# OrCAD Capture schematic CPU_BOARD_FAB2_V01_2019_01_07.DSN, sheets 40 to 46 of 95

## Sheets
40 012 RESET BLOCK DIAGRAM
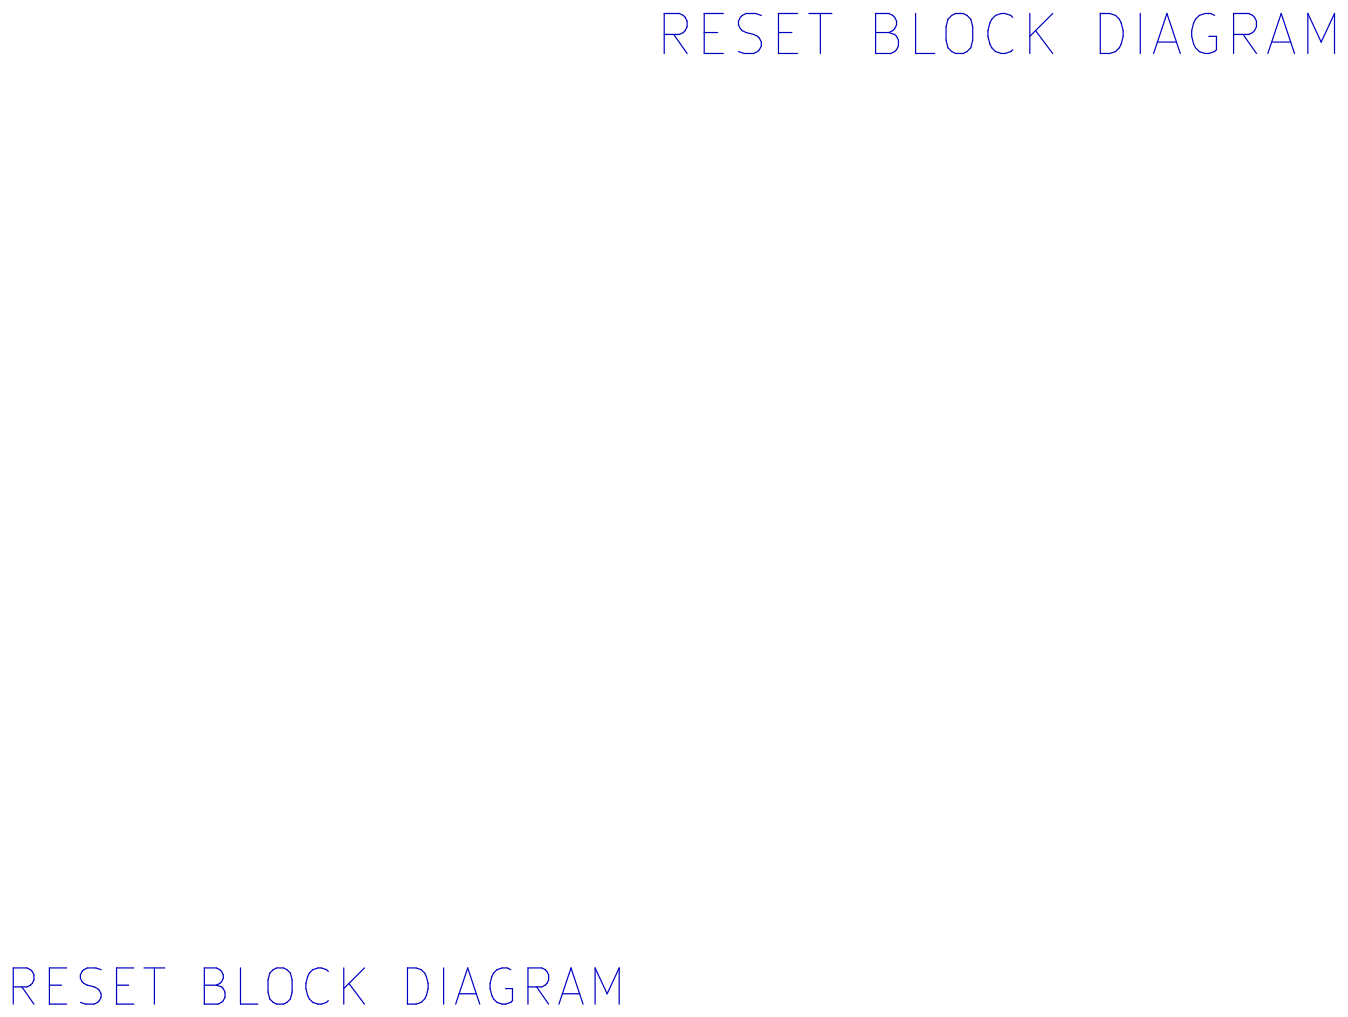
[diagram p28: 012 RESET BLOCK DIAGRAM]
41 016 BDE STRAPPING_1: size B
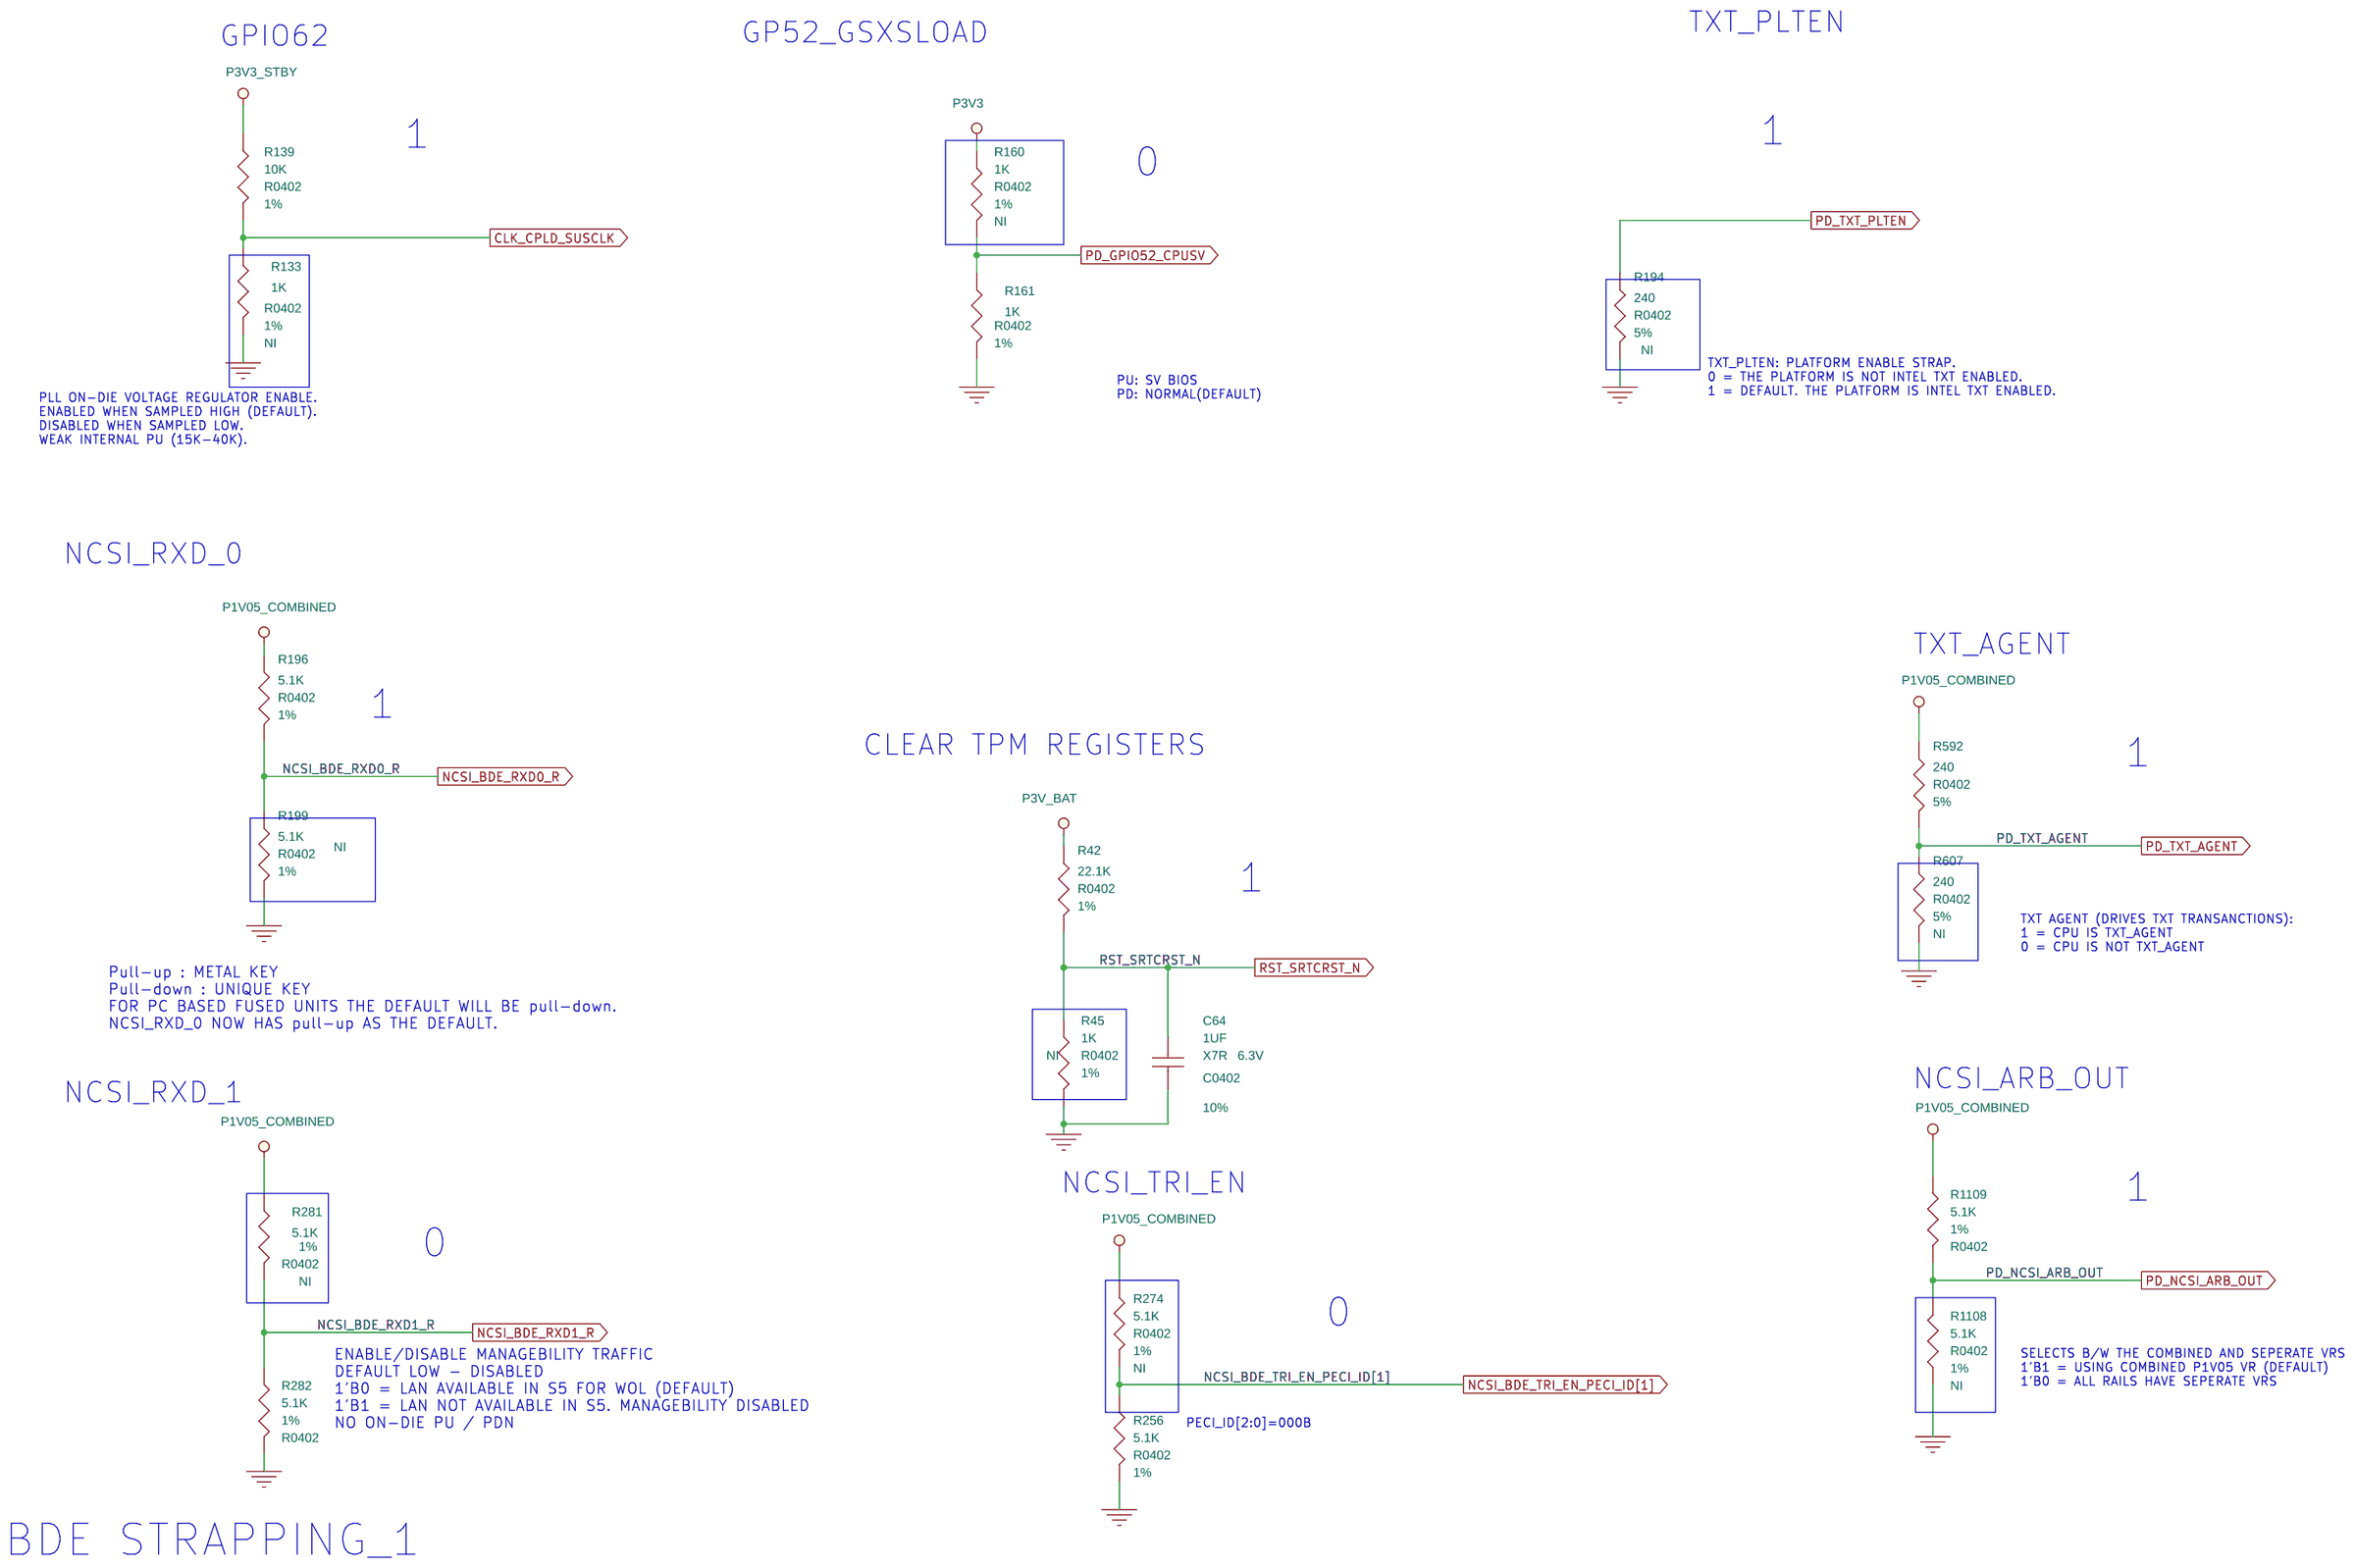
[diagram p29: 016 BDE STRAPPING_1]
42 017 BDE STRAPPING_2: size B
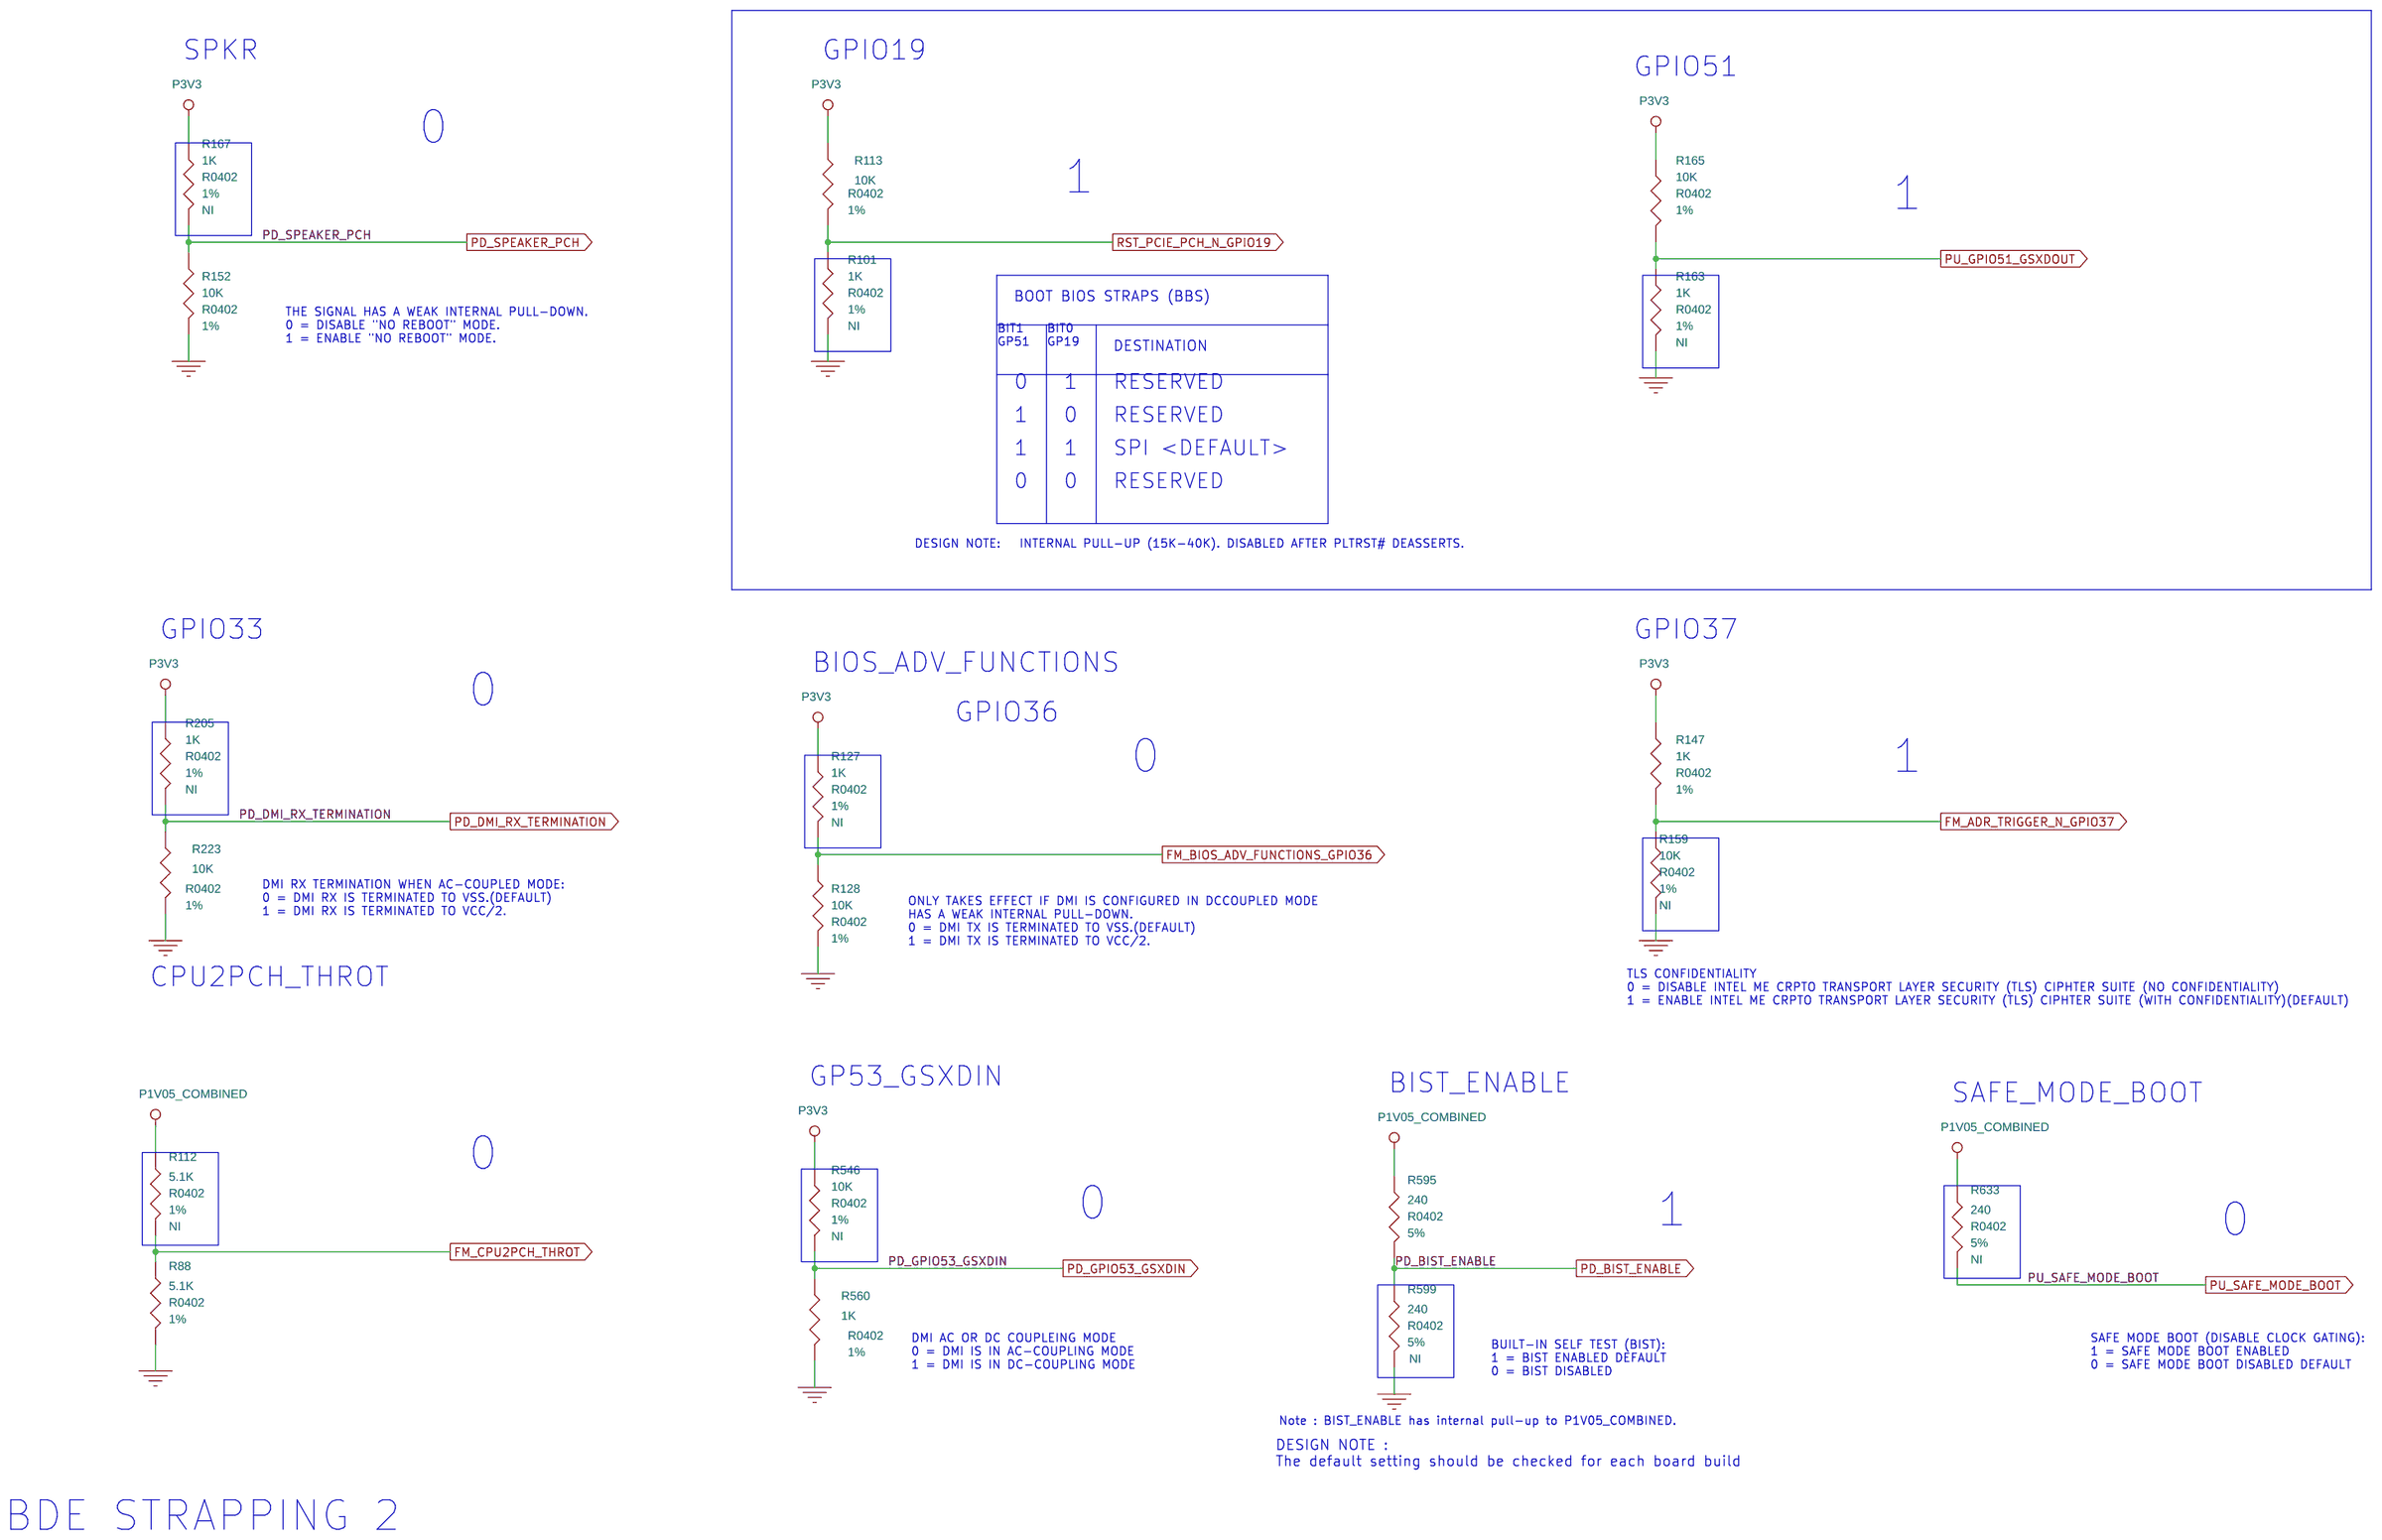
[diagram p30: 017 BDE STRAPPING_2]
43 018 BDX-DE DDR4 CHANNEL A: size B
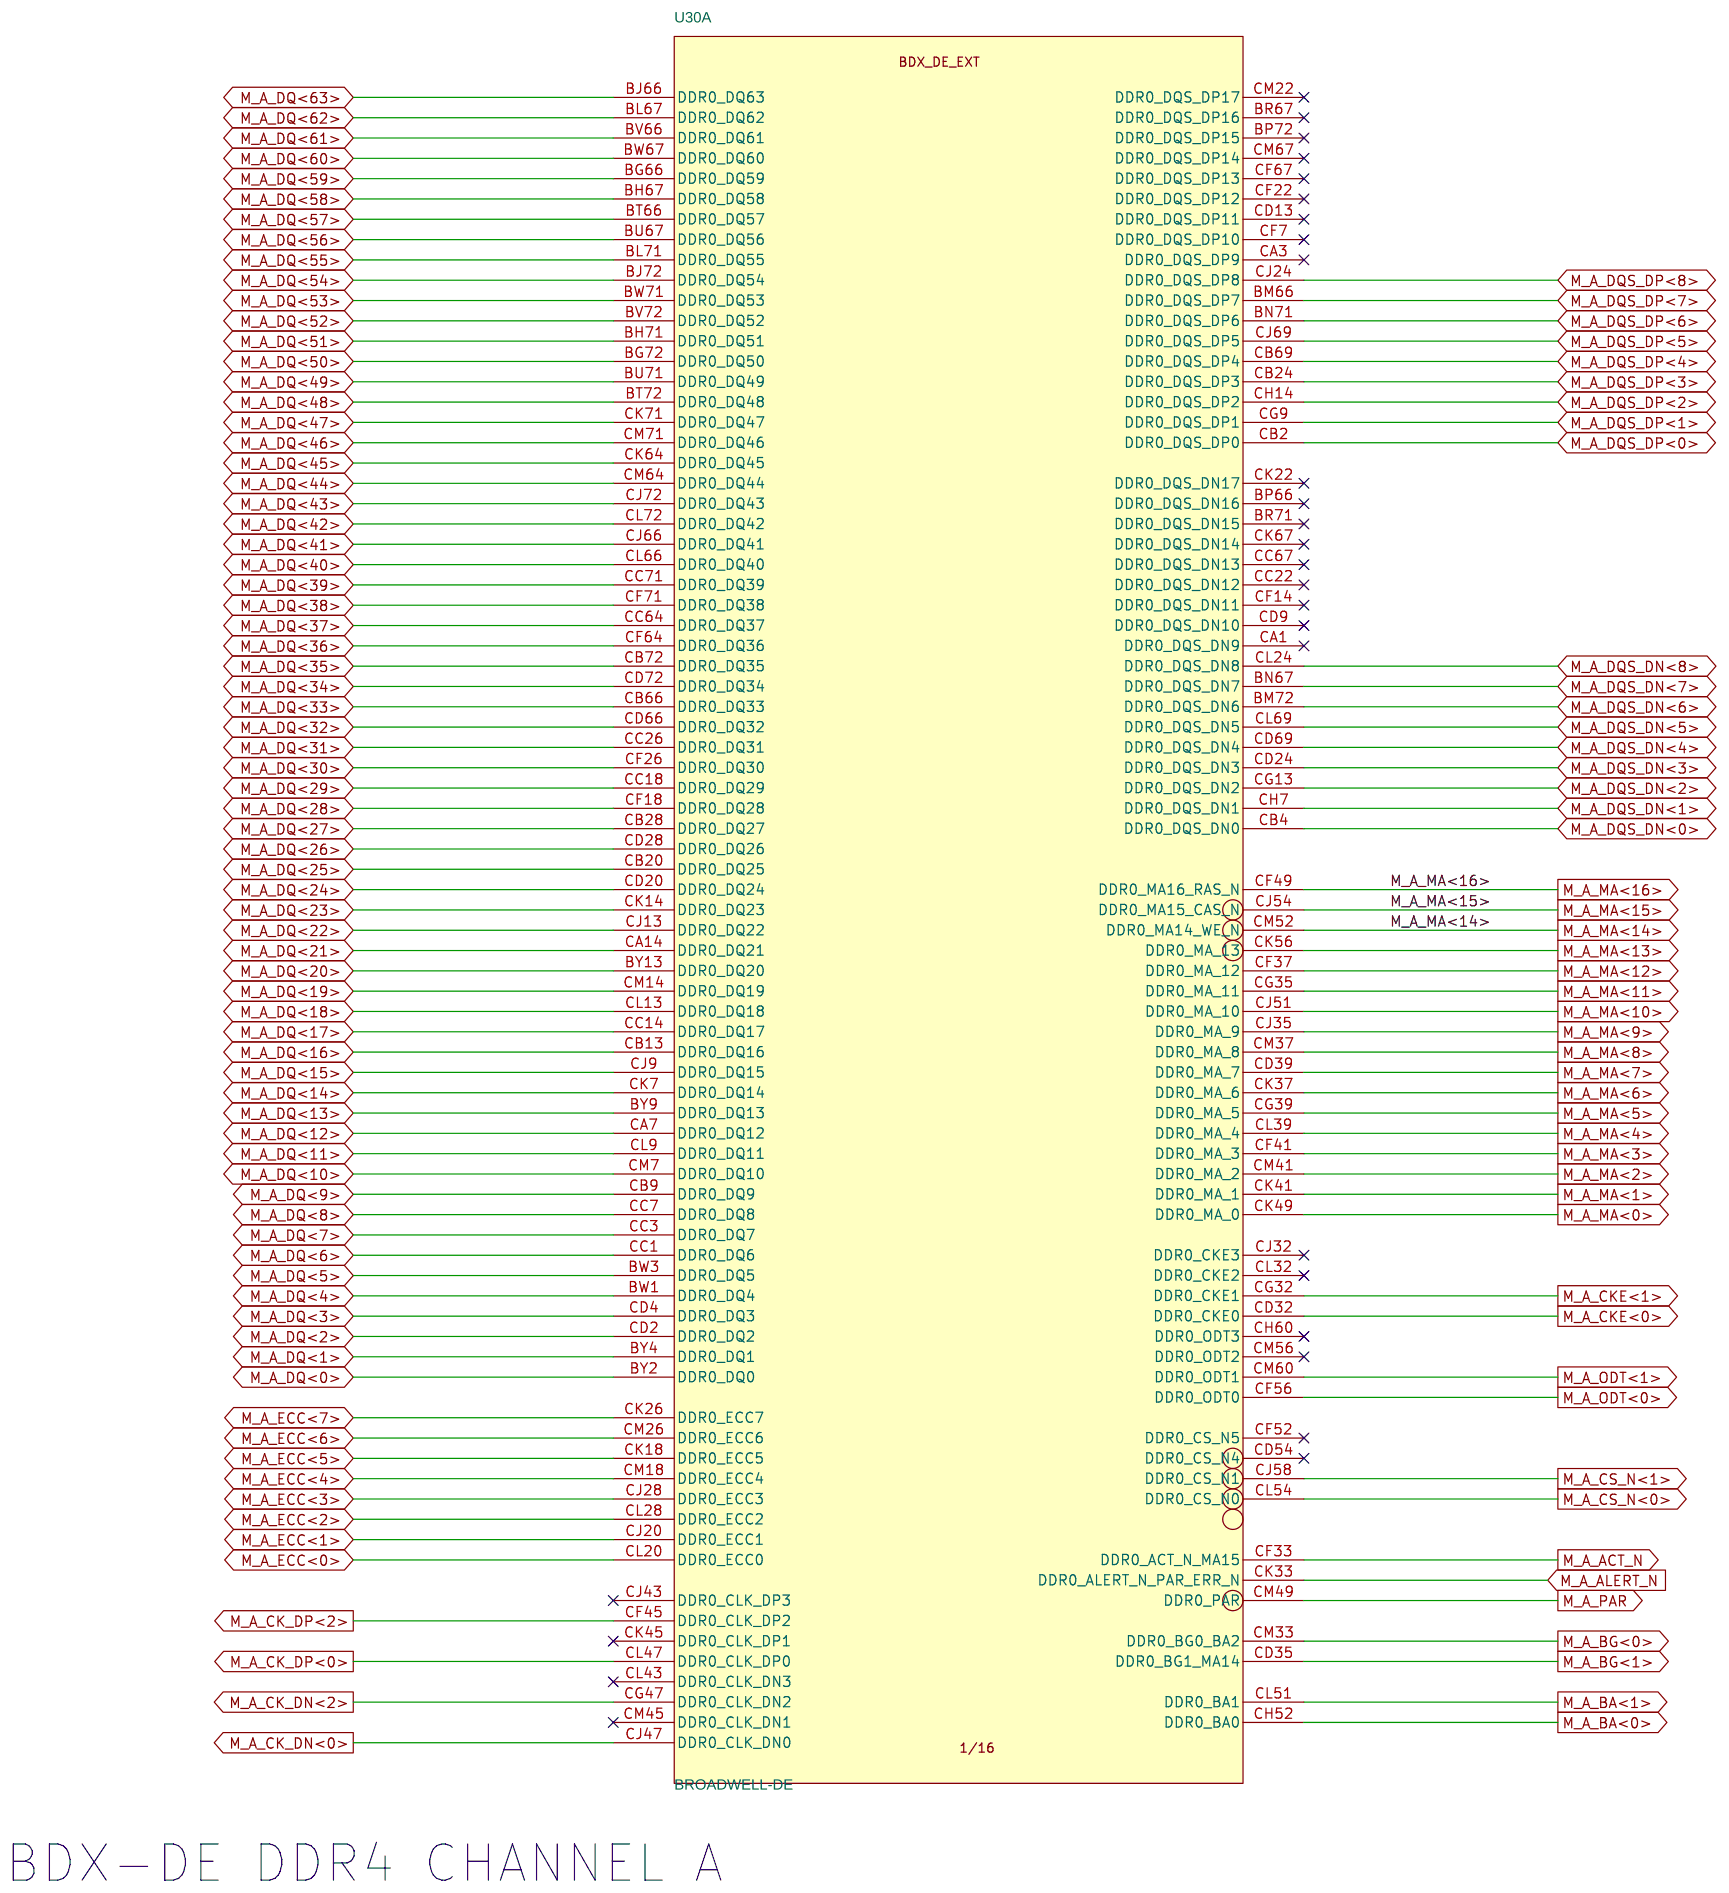
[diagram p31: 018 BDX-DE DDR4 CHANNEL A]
44 019 BDX-DE DDR4 CHANNEL B: size B
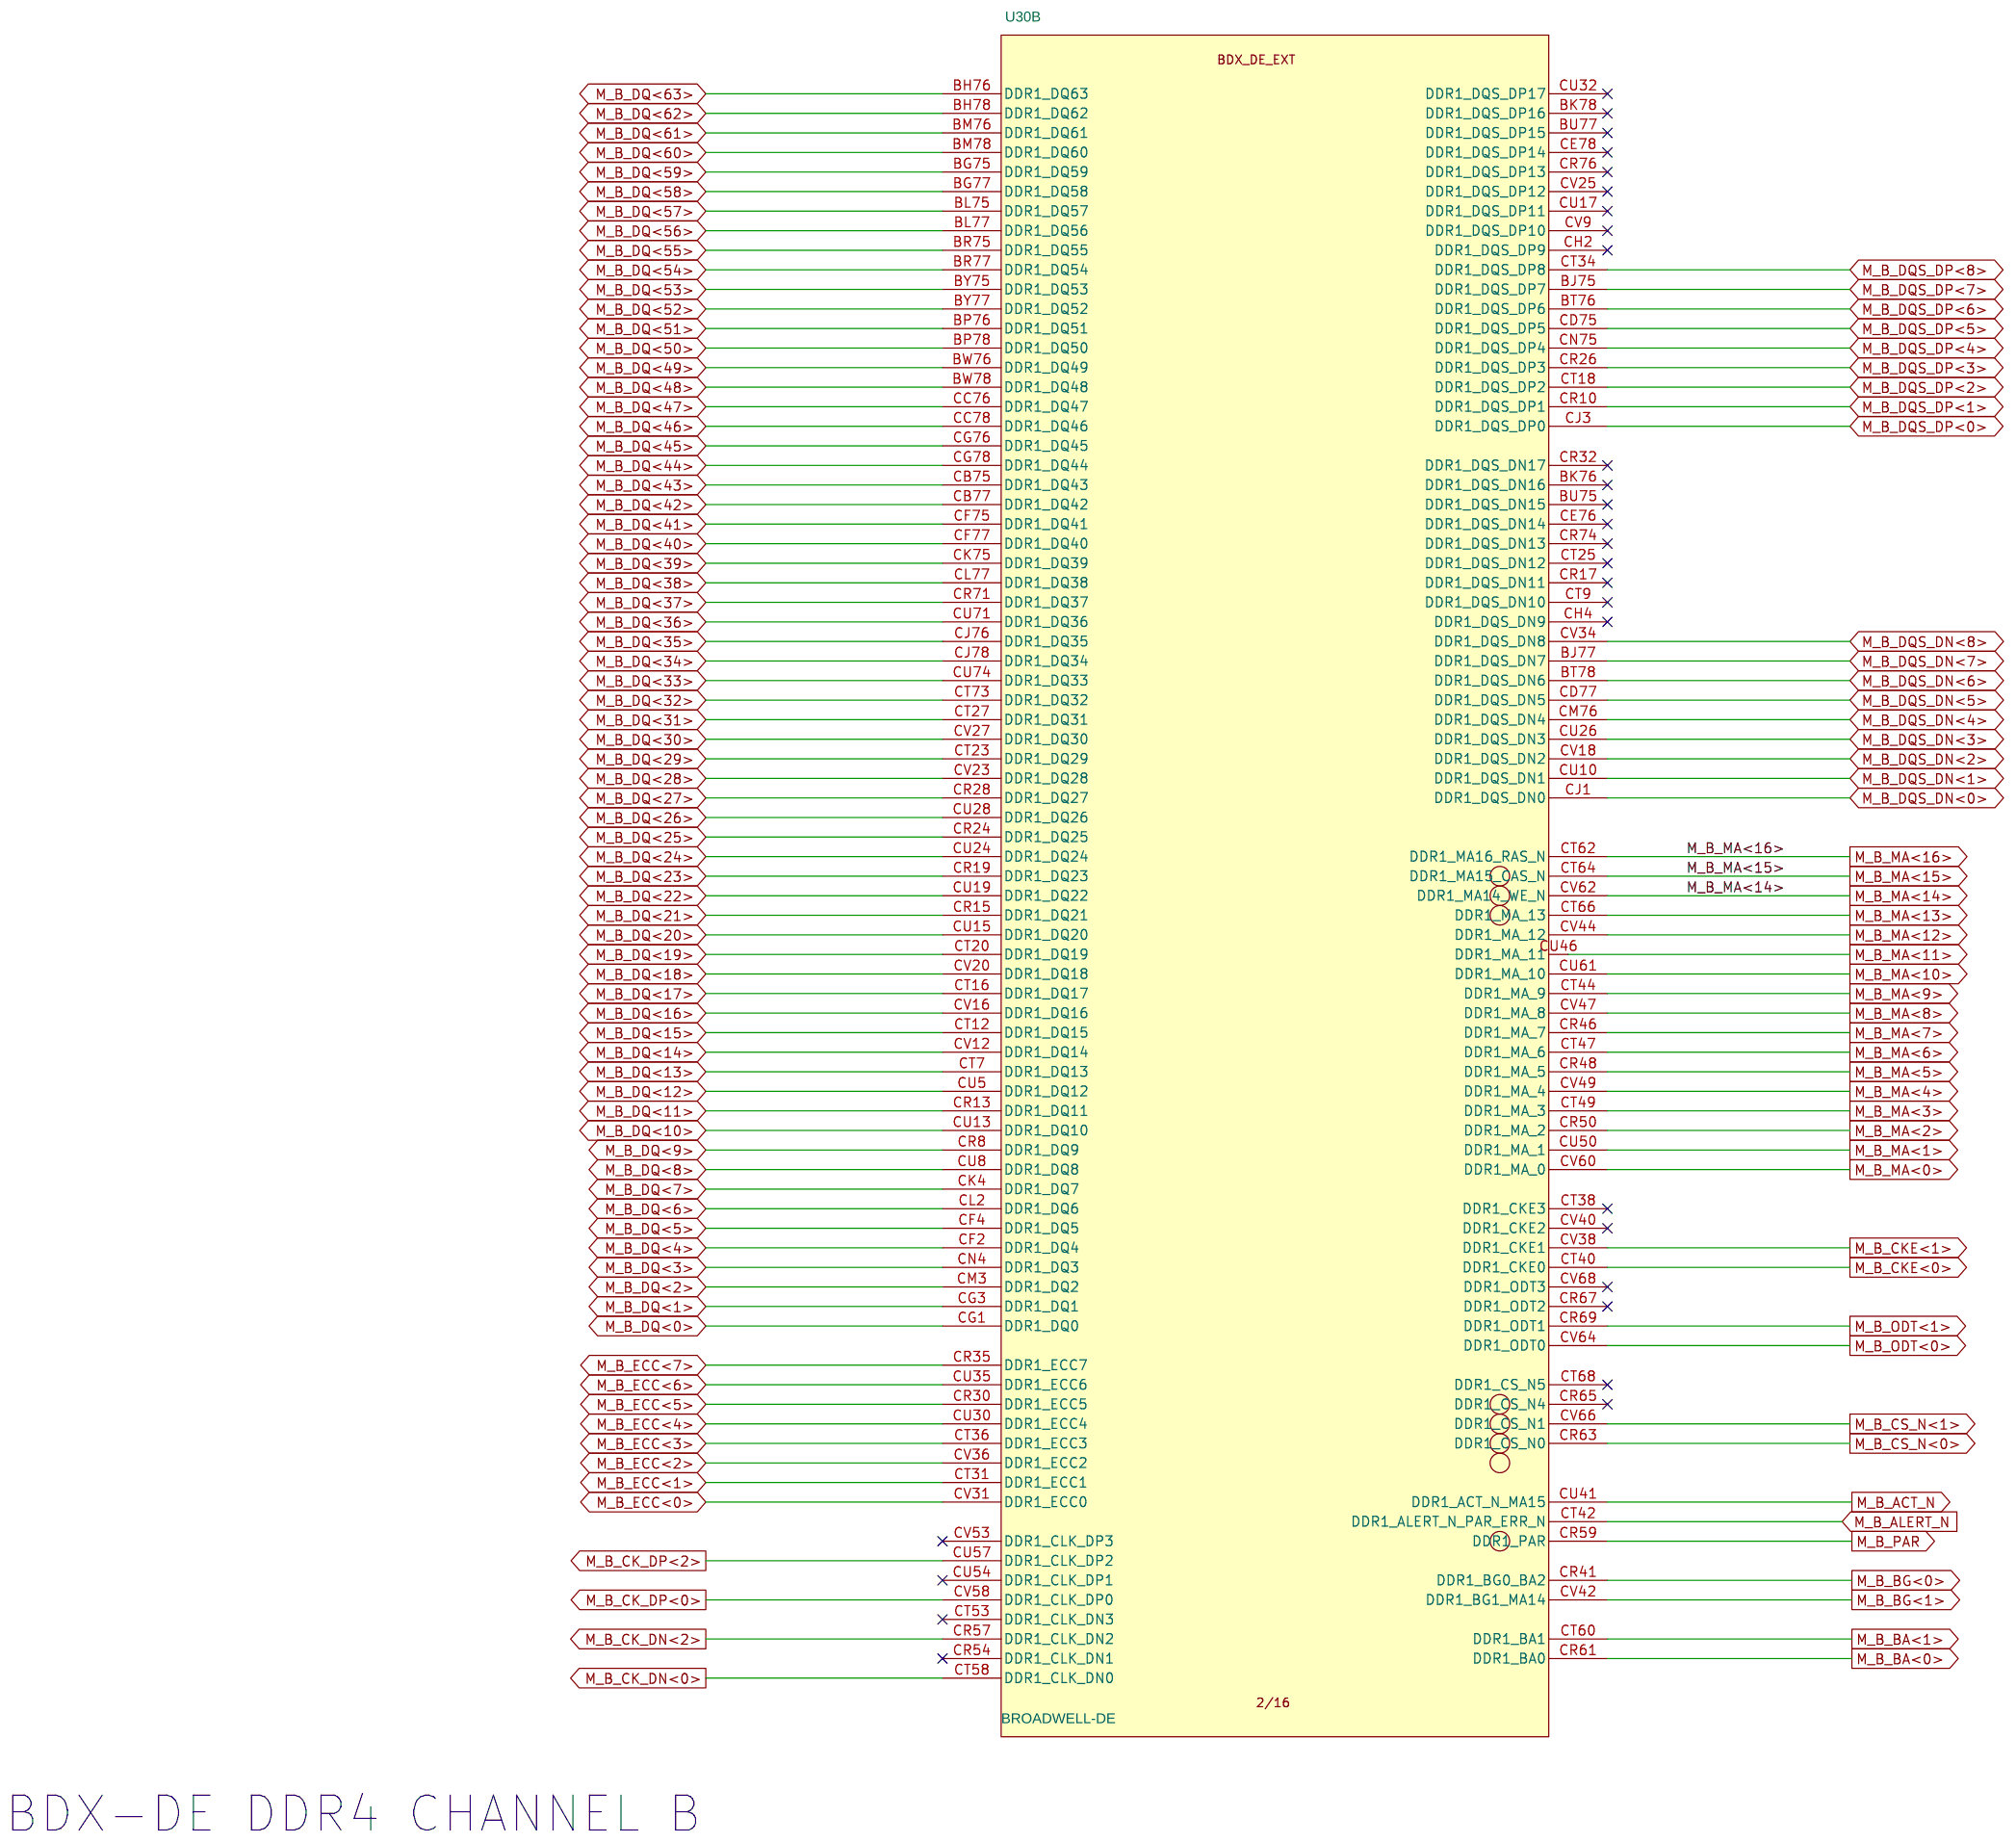
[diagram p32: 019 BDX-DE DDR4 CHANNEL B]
45 021 BDX-DE 10GBE LAN_1: size B
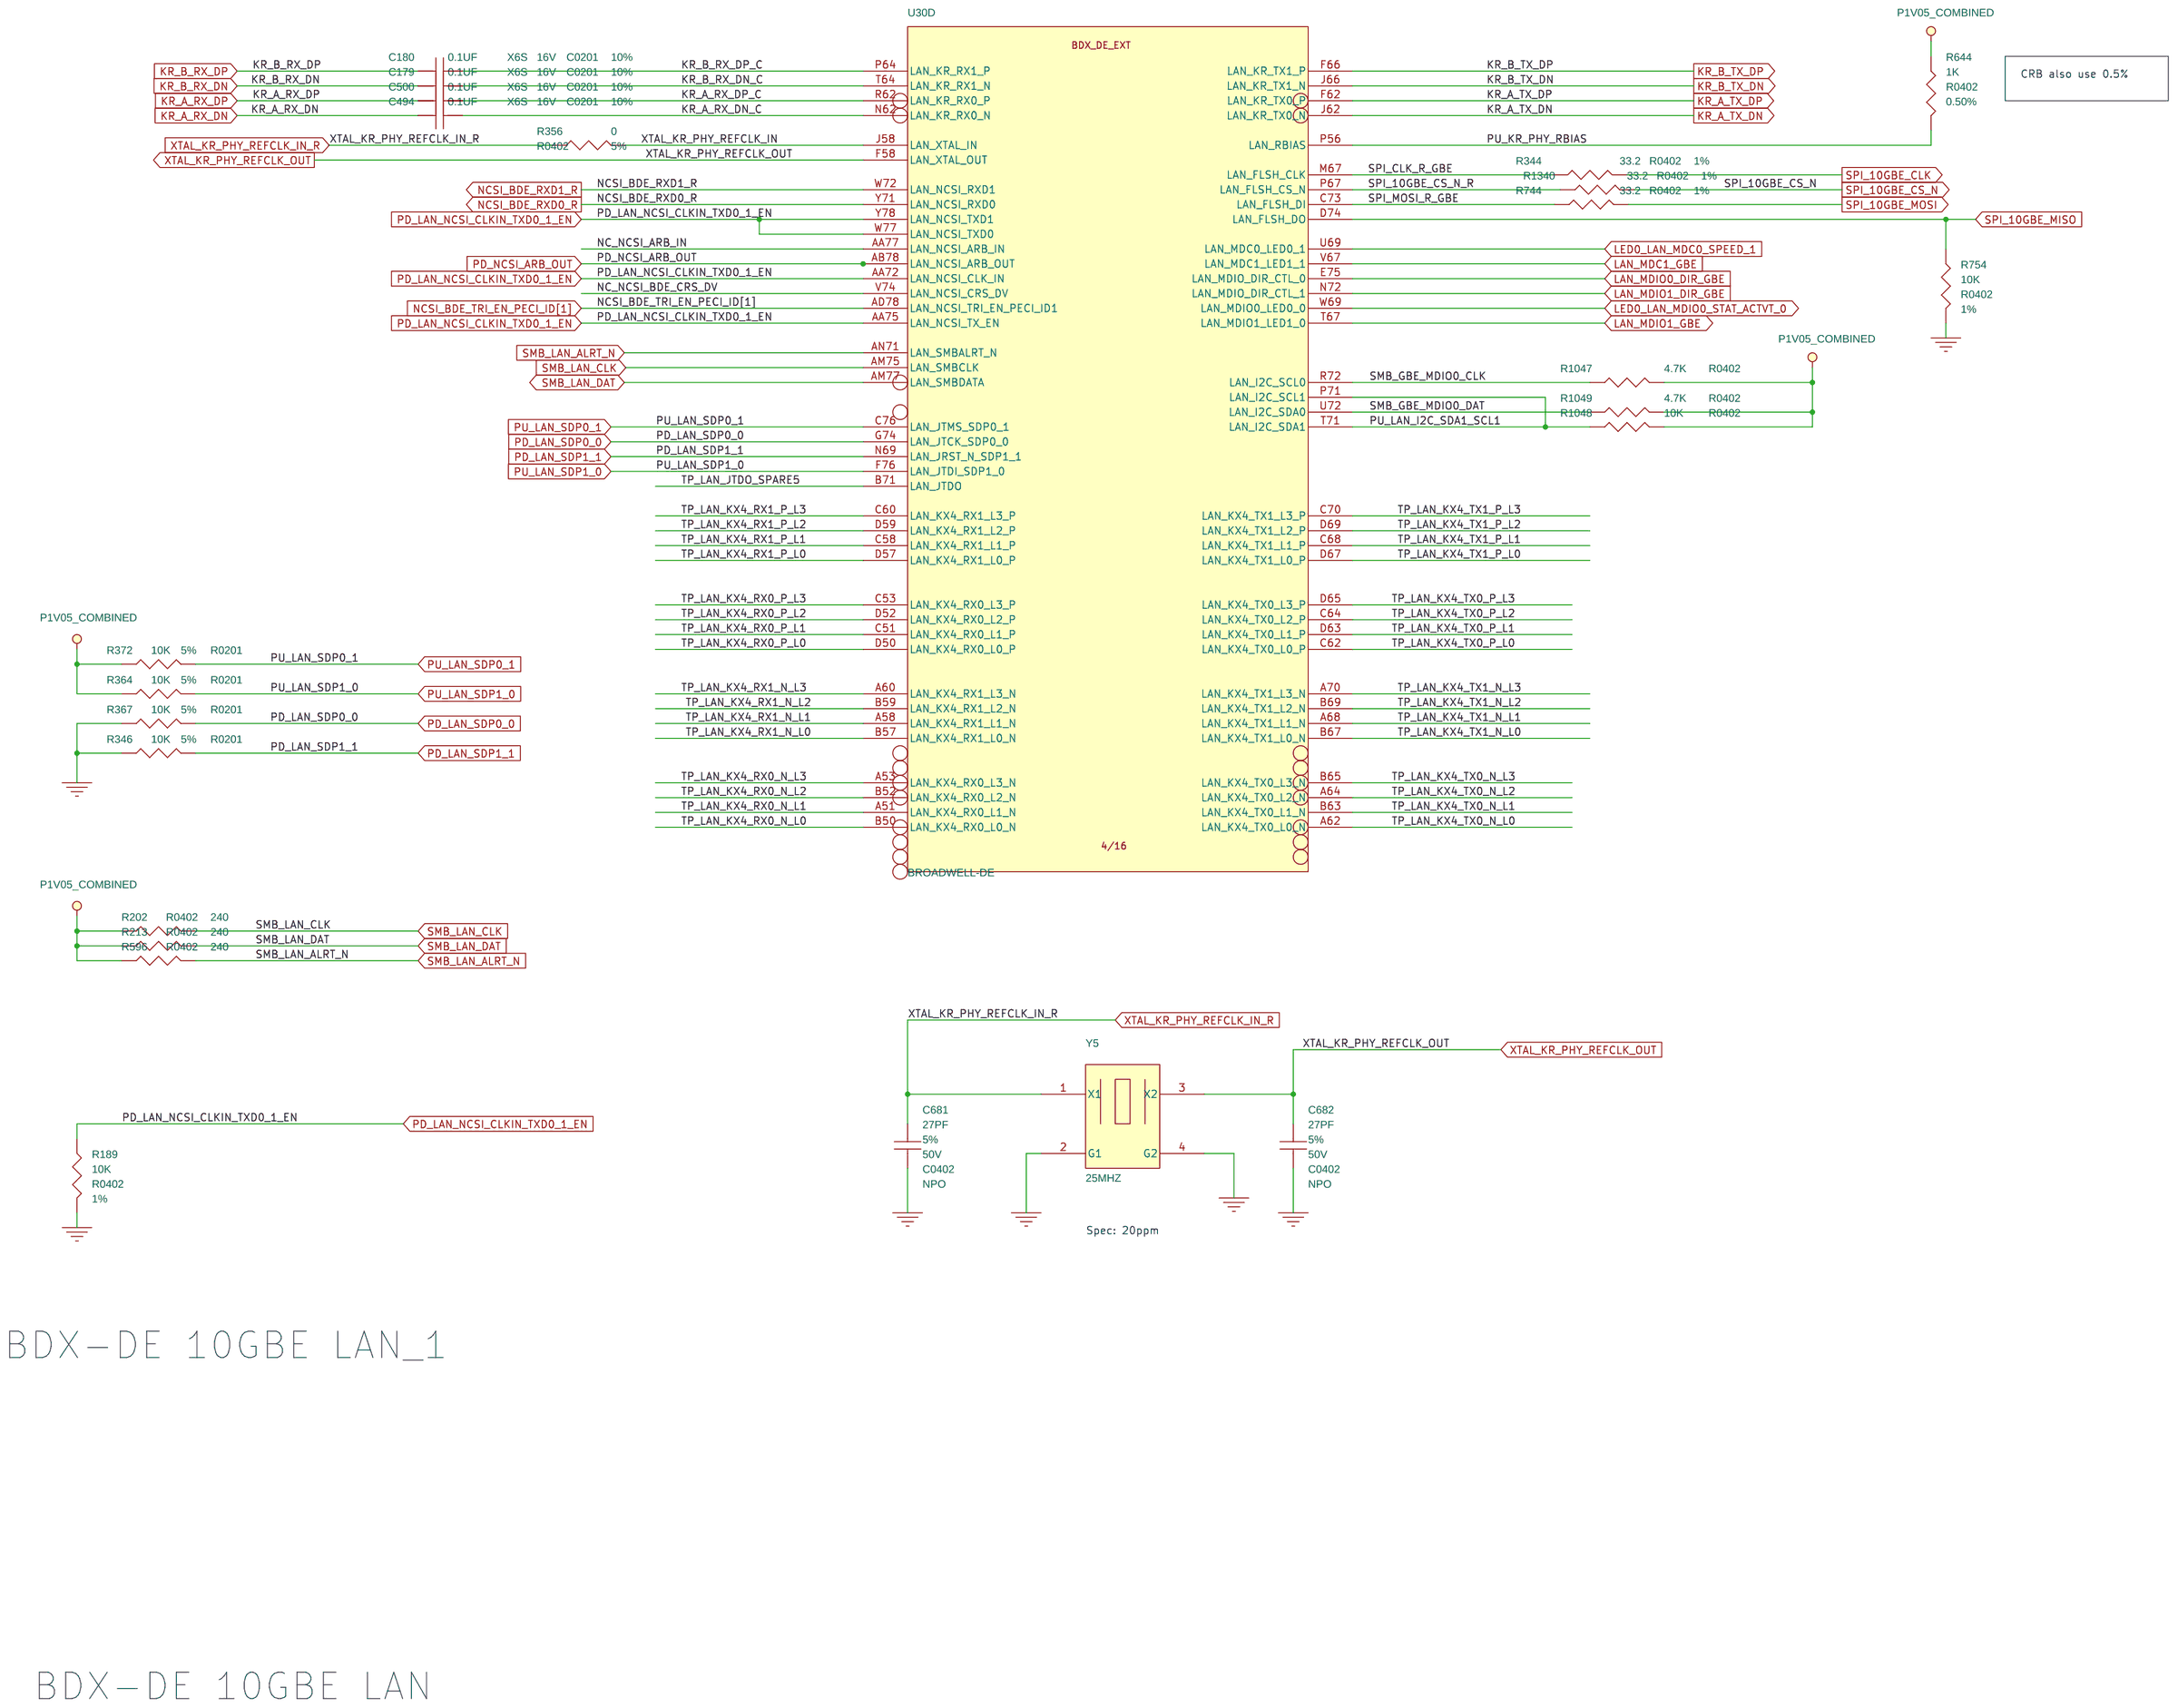
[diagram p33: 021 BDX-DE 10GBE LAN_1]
46 023 BDX-DE SATA, USB2, USB3: size B
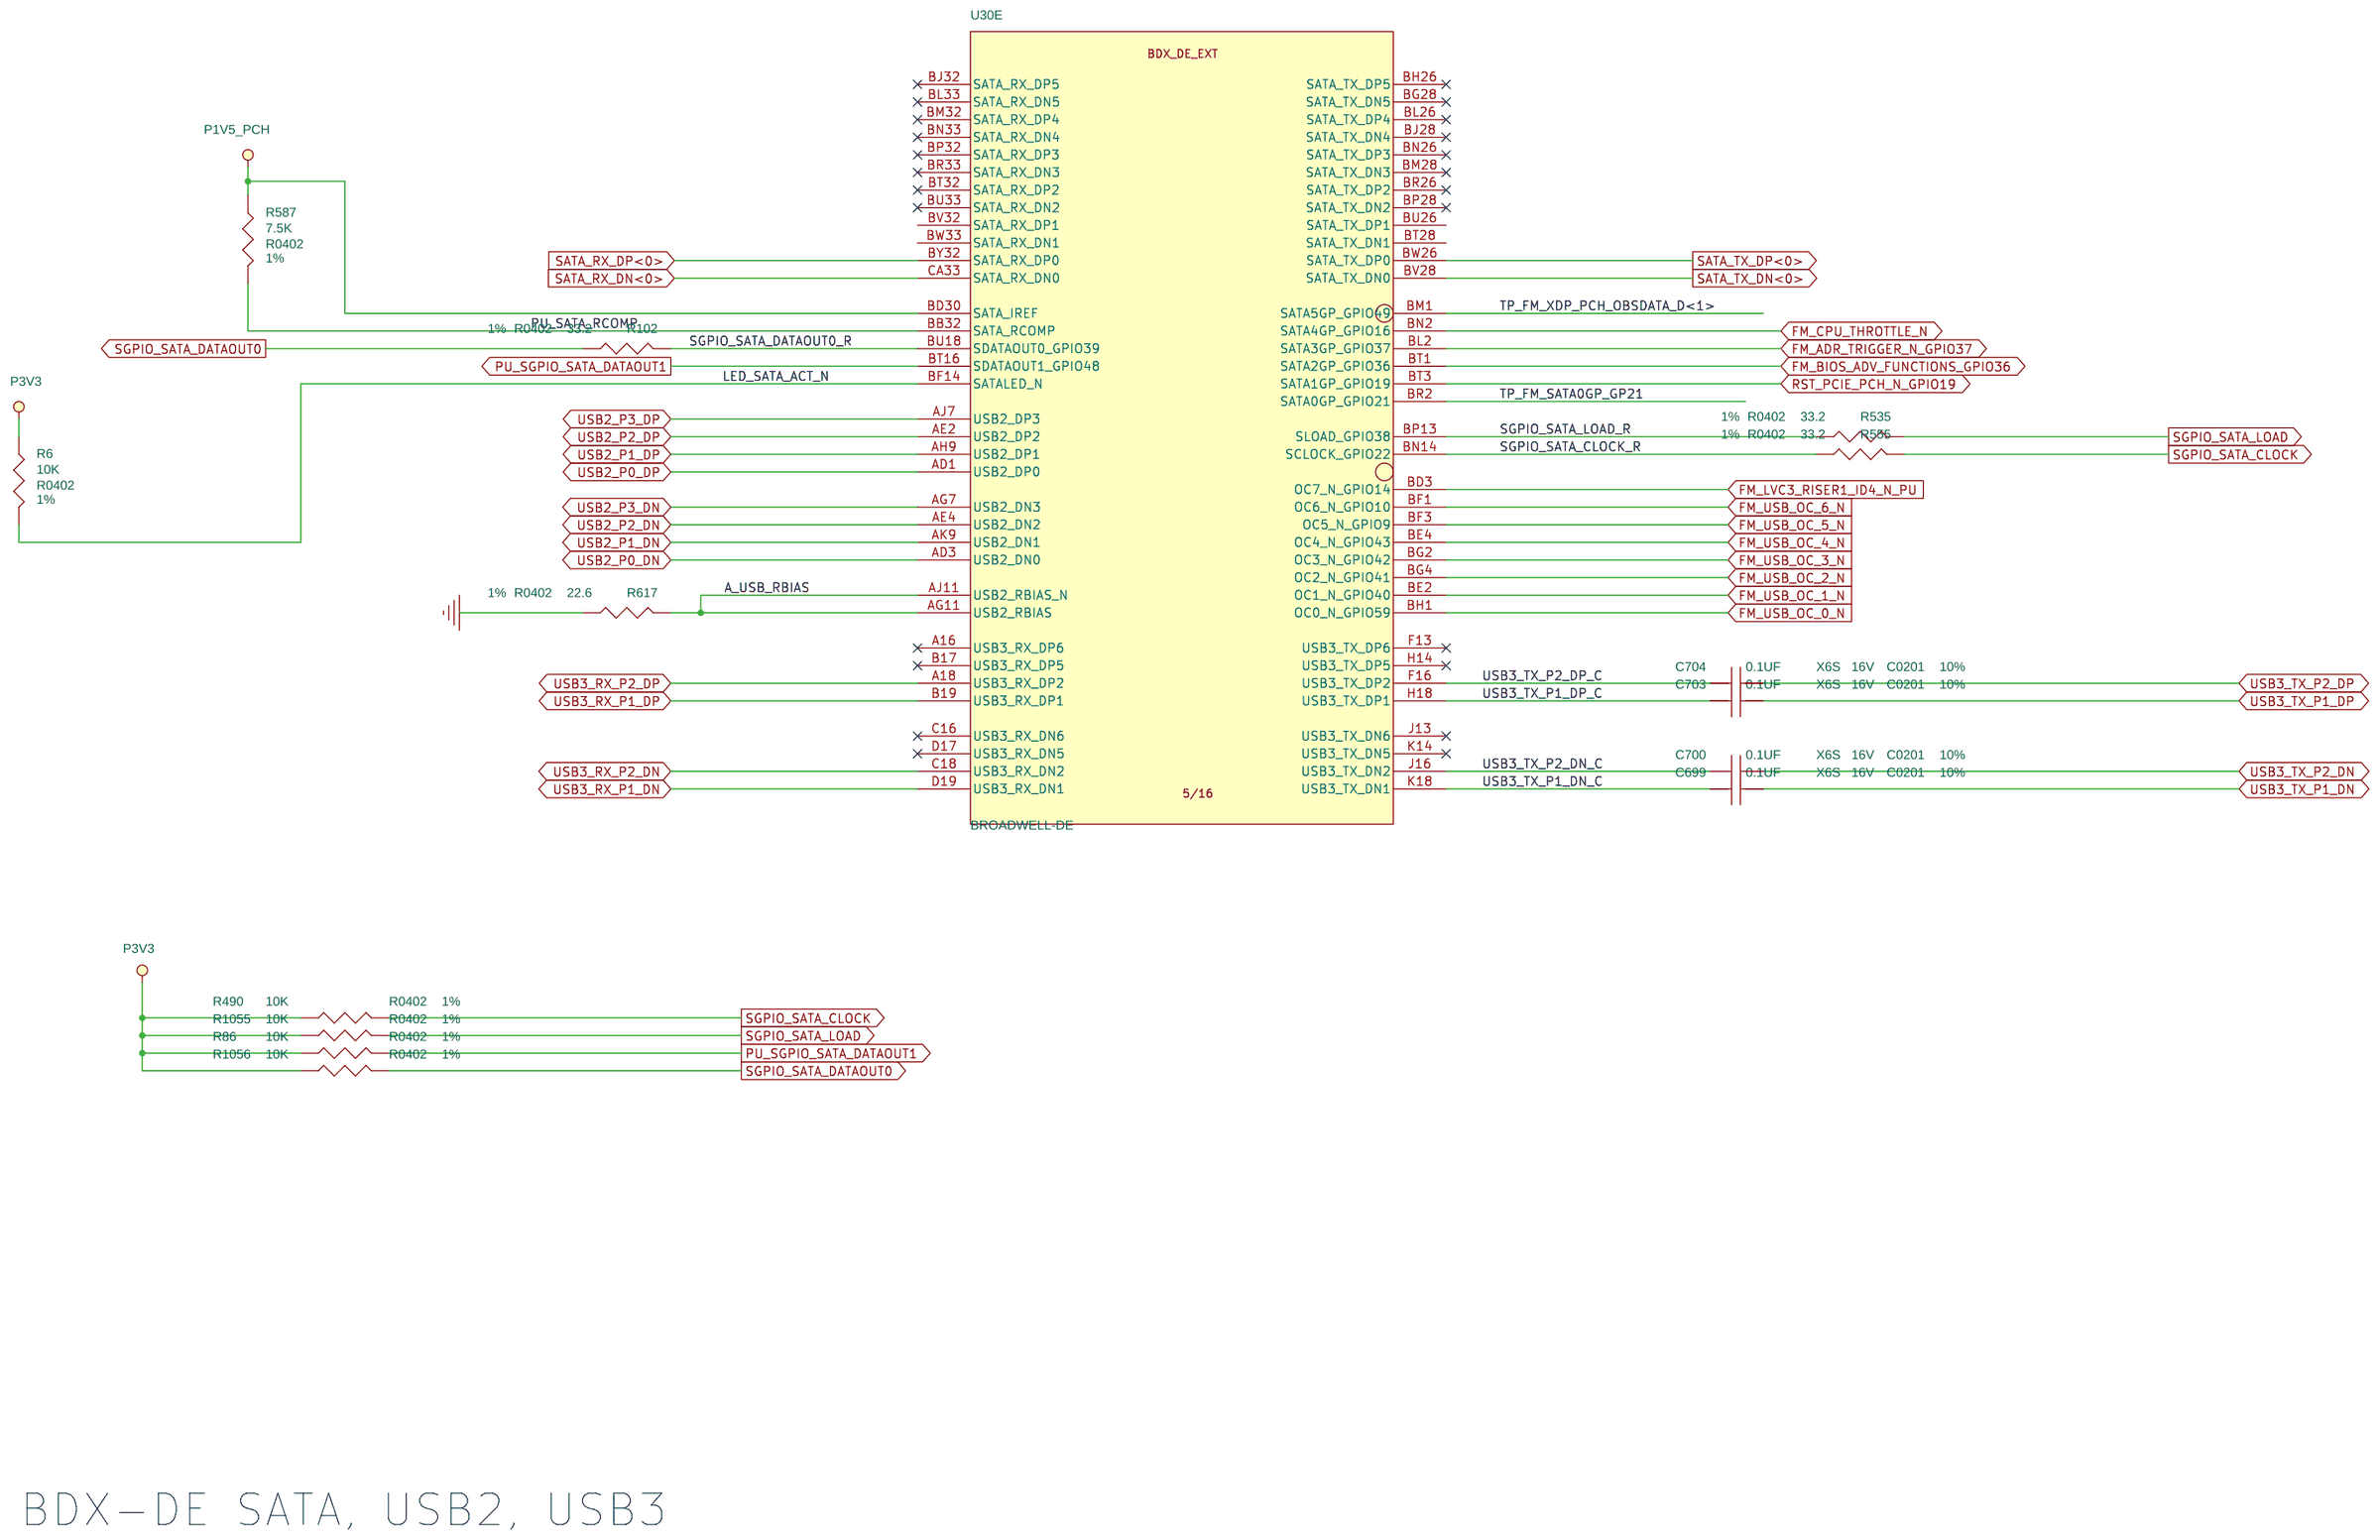
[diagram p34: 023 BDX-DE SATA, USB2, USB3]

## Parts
sheet 016 BDE STRAPPING_1
C64  1UF  [C0402]
R42  22.1K  [R0402]
R45  1K  [R0402]
R133  1K  [R0402]
R139  10K  [R0402]
R160  1K  [R0402]
R161  1K  [R0402]
R194  240  [R0402]
R196  5.1K  [R0402]
R199  5.1K  [R0402]
R256  5.1K  [R0402]
R274  5.1K  [R0402]
R281  5.1K  [R0402]
R282  5.1K  [R0402]
R592  240  [R0402]
R607  240  [R0402]
R1108  5.1K  [R0402]
R1109  5.1K  [R0402]
sheet 017 BDE STRAPPING_2
R88  5.1K  [R0402]
R101  1K  [R0402]
R112  5.1K  [R0402]
R113  10K  [R0402]
R127  1K  [R0402]
R128  10K  [R0402]
R147  1K  [R0402]
R152  10K  [R0402]
R159  10K  [R0402]
R163  1K  [R0402]
R165  10K  [R0402]
R167  1K  [R0402]
R205  1K  [R0402]
R223  10K  [R0402]
R546  10K  [R0402]
R560  1K  [R0402]
R595  240  [R0402]
R599  240  [R0402]
R633  240  [R0402]
sheet 021 BDX-DE 10GBE LAN_1
C179  0.1UF  [C0201]
C180  0.1UF  [C0201]
C494  0.1UF  [C0201]
C500  0.1UF  [C0201]
C681  27PF  [C0402]
C682  27PF  [C0402]
R189  10K  [R0402]
R202  240  [R0402]
R213  240  [R0402]
R344  33.2  [R0402]
R346  10K  [R0201]
R356  0  [R0402]
R364  10K  [R0201]
R367  10K  [R0201]
R372  10K  [R0201]
R596  240  [R0402]
R644  1K  [R0402]
R744  33.2  [R0402]
R754  10K  [R0402]
R1047  4.7K  [R0402]
R1048  10K  [R0402]
R1049  4.7K  [R0402]
R1340  33.2  [R0402]
Y5  25MHZ  [X_4S_8Z25000020_2-5X2]
sheet 023 BDX-DE SATA, USB2, USB3
C699  0.1UF  [C0201]
C700  0.1UF  [C0201]
C703  0.1UF  [C0201]
C704  0.1UF  [C0201]
R6  10K  [R0402]
R86  10K  [R0402]
R102  33.2  [R0402]
R490  10K  [R0402]
R535  33.2  [R0402]
R555  33.2  [R0402]
R587  7.5K  [R0402]
R617  22.6  [R0402]
R1055  10K  [R0402]
R1056  10K  [R0402]
U30  BROADWELL-DE  [BGA1667]  (sections A,B,C,D,E,F,G,H,I,J,K,L,M,N,O,P)

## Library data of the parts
C64 = CAP_NP: CAP CHIP 1U.6.3V(+-10%.X7R.0402); CLASS: DISCRETE; CMPLS_LVL: EP(V1); Data: MKP_LF_CAP SERIES.pdf; From_pj: T94-JEFF; Lifecycle: Comp-Approve; MATERIAL: X7R; Manuf_PN: MAG02X7R0J105K; Manuf_name: Matsuki Precision Ceramic Co.. Ltd.Matsuki Polymer Technology Co.. Ltd.; Manuftr: MKP; Part_Type: *LF_C0402; RD_CMPLS_LVL: EP(V1); TOLERANCE: 10%; VOLTAGE: 6.3V; fp_ECN: 0402 SERIES_LL34.xls
R42 = R: RES CHIP 22.1K 1/16W +-1%(0402); CLASS: DISCRETE; CMPLS_LVL: EP; Data: CYN-RR0510(0402) SERIES.pdf; From_pj: TU1-SUNGHSIN; Lifecycle: Comp-Approve; MATERIAL: CHIP; Manuf_PN: RR0510S-2212-FN; Manuf_name: CYNTEC CO.. LTD.; Manuftr: CYN; Part_Type: *LF_Resistor; Standard: ##; TOLERANCE: 1%; WATTAGE: 1/16W; fp_ECN: 0402 SERIES_LL34.xls
R45 R101 R127 R133 R160 R163 R167 R205 = R: RES CHIP 1K 1/16W +-1% (0402); CLASS: DISCRETE; CMPLS_LVL: EP; Data: WTC_LF_WR SERIES.pdf; Lifecycle: Comp-Approve; MATERIAL: CHIP; Manuf_PN: RR0510S-102-FN; Manuf_name: CYNTEC CO.. LTD.; Manuftr: CYN; Not_insert: NI; Part_Type: *LF_Resistor; Status: Preferred; TOLERANCE: 1%; WATTAGE: 1/16W; fp_ECN: 0402 SERIES_LL34.xls
R6 R86 R113 R128 R139 R152 R165 R189 R223 R490 R754 R1048 R1055 R1056 = R: RES CHIP 10K 1/16W +-1% (0402); CLASS: DISCRETE; CMPLS_LVL: EP; Data: WTC_LF_WR SERIES.pdf; From_pj: S82; Lifecycle: Comp-Approve; MATERIAL: CHIP; Manuf_PN: RR0510S-103-FN; Manuf_name: CYNTEC CO.. LTD.; Manuftr: CYN; Part_Type: *LF_Resistor; Status: Preferred; TOLERANCE: 1%; WATTAGE: 1/16W; fp_ECN: 0402 SERIES_LL34.xls
R147 R161 R560 = R: RES CHIP 1K 1/16W +-1% (0402); CLASS: DISCRETE; CMPLS_LVL: EP; Data: WTC_LF_WR SERIES.pdf; Lifecycle: Comp-Approve; MATERIAL: CHIP; Manuf_PN: RR0510S-102-FN; Manuf_name: CYNTEC CO.. LTD.; Manuftr: CYN; Part_Type: *LF_Resistor; Status: Preferred; TOLERANCE: 1%; WATTAGE: 1/16W; fp_ECN: 0402 SERIES_LL34.xls
R194 R599 R607 R633 = R: RES CHIP 240 1/16W +-5%(0402); CLASS: DISCRETE; CMPLS_LVL: EP; Data: YGO_RC0402 SERIES.pdf; From_pj: TU1B-MARTIN; Lifecycle: Comp-Approve; MATERIAL: CHIP; Manuf_PN: RC0402JR-07240RL; Manuf_name: YAGEO CORPORATION; Manuftr: YGO; Not_insert: NI; Part_Type: *LF_Resistor; RD_CMPLS_LVL: EP; TOLERANCE: 5%; WATTAGE: 1/16W; fp_ECN: 0402 SERIES_LL34.xls
R88 R196 R256 R282 R1109 = R: RES CHIP 5.1K 1/16W +-1%(0402); CLASS: DISCRETE; CMPLS_LVL: EP; Data: MAT_LF_RES SERIES.pdf; From_pj: S10-ANTONY; Lifecycle: Comp-Approve; MATERIAL: CHIP; Manuf_PN: RR0510S-512-FN; Manuf_name: CYNTEC CO.. LTD.; Manuftr: CYN; Part_Type: *LF_Resistor; Status: Normal; TOLERANCE: 1%; WATTAGE: 1/16W; fp_ECN: 0402 SERIES_LL34.xls
R112 R199 R274 R281 = R: RES CHIP 5.1K 1/16W +-1%(0402); CLASS: DISCRETE; CMPLS_LVL: EP; Data: MAT_LF_RES SERIES.pdf; From_pj: S10-ANTONY; Lifecycle: Comp-Approve; MATERIAL: CHIP; Manuf_PN: RR0510S-512-FN; Manuf_name: CYNTEC CO.. LTD.; Manuftr: CYN; Not_insert: NI; Part_Type: *LF_Resistor; Status: Normal; TOLERANCE: 1%; WATTAGE: 1/16W; fp_ECN: 0402 SERIES_LL34.xls
R202 R213 R592 R595 R596 = R: RES CHIP 240 1/16W +-5%(0402); CLASS: DISCRETE; CMPLS_LVL: EP; Data: YGO_RC0402 SERIES.pdf; From_pj: TU1B-MARTIN; Lifecycle: Comp-Approve; MATERIAL: CHIP; Manuf_PN: RC0402JR-07240RL; Manuf_name: YAGEO CORPORATION; Manuftr: YGO; Part_Type: *LF_Resistor; RD_CMPLS_LVL: EP; TOLERANCE: 5%; WATTAGE: 1/16W; fp_ECN: 0402 SERIES_LL34.xls
R1108 = R: RES CHIP 5.1K 1/16W +-1%(0402); CLASS: DISCRETE; CMPLS_LVL: EP; Data: MAT_LF_RES SERIES.pdf; From_pj: S10-ANTONY; Lifecycle: Comp-Approve; MATERIAL: CHIP; Manuf_PN: RR0510S-512-FN; Manuf_name: CYNTEC CO.. LTD.; Manufacturer: RLC; Manuftr: CYN; Not_insert: NI; Part_Type: *LF_Resistor; Status: Normal; TOLERANCE: 1%; WATTAGE: 1/16W; fp_ECN: 0402 SERIES_LL34.xls; top_bot: TOP
R159 R546 = R: RES CHIP 10K 1/16W +-1% (0402); CLASS: DISCRETE; CMPLS_LVL: EP; Data: WTC_LF_WR SERIES.pdf; From_pj: S82; Lifecycle: Comp-Approve; MATERIAL: CHIP; Manuf_PN: RR0510S-103-FN; Manuf_name: CYNTEC CO.. LTD.; Manuftr: CYN; Not_insert: NI; Part_Type: *LF_Resistor; Status: Preferred; TOLERANCE: 1%; WATTAGE: 1/16W; fp_ECN: 0402 SERIES_LL34.xls
C179 C180 C494 C500 C699 C700 C703 C704 = CAP_NP: CAP CHIP 0.1UF 16V(+-10%,X6S,0201); CLASS: DISCRETE; CMPLS_LVL: EP(V1); Data: TAY_EMK063AC6104KP.pdf; From_pj: S2P-SEAN; Lifecycle: Comp-Approve; MATERIAL: X6S; Manuf_PN: EMK063AC6104KP-F; Manuf_name: TAIYO YUDEN CO.,LTD; Manuftr: TAY; Part_Type: *LF_C0201; RD_CMPLS_LVL: EP(V1); TOLERANCE: 10%; VOLTAGE: 16V; fp_ECN: DCN-all 0201 RCL part.doc
C681 C682 = CAP_NP: CAP CHIP 27P 50V(+-5% NPO 0402); CLASS: DISCRETE; CMPLS_LVL: EP; Data: MUR_LF_CAP SERIES_1.pdf; From_pj: LB6-JAMES; Lifecycle: Comp-Approve; MATERIAL: NPO; Manuf_PN: GRM1555C1H270J; Manuf_name: MURATA ERIE N.A. INC TAIWAN BRANCH Okayama Murata Mfg.Co..Ltd. Wakura Murata Mfg; Manuftr: MUR; Part_Type: *LF_C0402; TOLERANCE: 5%; VOLTAGE: 50V; fp_ECN: 0402 SERIES_LL34.xls
R344 R744 R1340 = R: RES CHIP 33.2 1/16W +-1%(0402); CLASS: DISCRETE; CMPLS_LVL: EP; Data: CYN_LF_RL SERIES.pdf; From_pj: A06-EDISON; Lifecycle: Comp-Approve; MATERIAL: CHIP; Manuf_PN: RR0510S-33R2-FN; Manuf_name: CYNTEC CO.. LTD.; Manufacturer: CYN; Manuftr: CYN; Part_Type: *LF_Resistor; TOLERANCE: 1%; WATTAGE: 1/16W; fp_ECN: 0402 SERIES_LL34.xls; top_bot: TOP
R346 R364 R367 R372 = R: RES CHIP 10K 1/20W +-5%(0201); CLASS: DISCRETE; CMPLS_LVL: EP(V1); Data: WTC_WR02X103 JAL_REVL.pdf; From_pj: F07-HENRY; Lifecycle: Comp-Approve; MATERIAL: CHIP; Manuf_PN: WR02X103 JAL; Manuf_name: WALSIN TECHNOLOGY CORPORATION; Manuftr: WTC; Part_Type: *LF_Resistor; RD_CMPLS_LVL: EP(V1); TOLERANCE: 5%; WATTAGE: 1/20W; fp_ECN: DCN-ALL 0201 RCL PART.doc
R356 = R: RESISTOR CHIP 0 1/16W +-5%(0402); CLASS: DISCRETE; CMPLS_LVL: EP; Data: WTC_LF_WR SERIES.pdf; Lifecycle: Comp-Approve; MATERIAL: CHIP; Manuf_PN: RR0510X-000-XN; Manuf_name: CYNTEC CO.. LTD.; Manuftr: CYN; Part_Type: *LF_Resistor; Status: Preferred; TOLERANCE: 5%; WATTAGE: 1/16W; fp_ECN: 0402 SERIES_LL34.xls
R644 = R: RES CHIP 1K 1/16W +-0.5% (0402); CLASS: DISCRETE; CMPLS_LVL: EP(V1); Data: YGO_R-Chip-Datasheet.pdf; From_pj: T2A-TONY; Lifecycle: Comp-Approve; MATERIAL: CHIP; Manuf_PN: RT0402DRE071KL; Manuf_name: YAGEO CORPORATION; Manuftr: YGO; Part_Type: *LF_Resistor; RD_CMPLS_LVL: EP(V1); Standard: ##; TOLERANCE: 0.50%; WATTAGE: 1/16W; fp_ECN: 0402 SERIES_LL34.xls
R1047 R1049 = R: RES CHIP 4.7K 1/16W +-5% (0402); CLASS: DISCRETE; CMPLS_LVL: EP; Data: WTC_LF_WR SERIES.pdf; Lifecycle: Comp-Approve; MATERIAL: CHIP; Manuf_PN: RR0510S-472-JN; Manuf_name: CYNTEC CO.. LTD.; Manuftr: CYN; Part_Type: *LF_Resistor; Status: Preferred; TOLERANCE: 5%; WATTAGE: 1/16W; fp_ECN: 0402 SERIES_LL34.xls
Y5 = X_4S_CX3225SB25000D0FPLCC: XTAL SMD 25MHZ(10PPM,18PF)8Z25000020; CLASS: IO; Data: TXC_8Z25000020.pdf; From_pj: F09-TONY; Lifecycle: P/N Release; MATERIAL: MISC; Manuf_PN: 8Z25000020; Manuf_name: TAIWAN X'TAL CORPATION (TXC Corporation); Manuftr: TXC; Part_Type: *LF_Misc; RD_CMPLS_LVL: EP(V1); Standard: Potential
R102 R535 R555 = R: RES CHIP 33.2 1/16W +-1%(0402); CLASS: DISCRETE; CMPLS_LVL: EP; Data: CYN_LF_RL SERIES.pdf; From_pj: A06-EDISON; Lifecycle: Comp-Approve; MATERIAL: CHIP; Manuf_PN: RR0510S-33R2-FN; Manuf_name: CYNTEC CO.. LTD.; Manuftr: CYN; Part_Type: *LF_Resistor; TOLERANCE: 1%; WATTAGE: 1/16W; fp_ECN: 0402 SERIES_LL34.xls
R587 = R: RES CHIP 7.5K 1/16W +-1% (0402); CLASS: DISCRETE; CMPLS_LVL: EP; Data: WTC_LF_WR SERIES-4.pdf; From_pj: S93-MARTIN; MATERIAL: CHIP; Manuf_PN: WR04X7501FTL; Manuf_name: WALSIN TECHNOLOGY CORPORATION; Manuftr: WTC; Part_Type: *LF_Resistor; TOLERANCE: 1%; WATTAGE: 1/16W; fp_ECN: 0402 SERIES_LL34.xls
R617 = R: RES CHIP 22.6 1/16W +-1%(0402); CLASS: DISCRETE; CMPLS_LVL: EP; Data: WTC_LF_WR SERIES.pdf; MATERIAL: CHIP; Manuf_PN: RR0510S-22R6-FN; Manuf_name: CYNTEC CO.. LTD.; Manuftr: CYN; Part_Type: *LF_Resistor; Status: Preferred; TOLERANCE: 1%; WATTAGE: 1/16W; fp_ECN: 0402 SERIES_LL34.xls
U30 = BROADWELLDE: CPU(1667P)Broadwell-DE (FCBGA); CLASS: IC; Data: INT_Broadwell-DE_REV0_75.pdf; From_pj: S1M-MANSON; MATERIAL: IC; Manuf_name: INTEGRATED DEVICE TECHNOLOGY,INC.; Manuftr: INT; Part_Type: Tmp; Color: Default; Location X-Coordinate: 0; Location Y-Coordinate: 0; Power Pins Visible: False; Primitive: DEFAULT

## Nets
GND: C64.2 C681.2 C682.2 R45.2 R88.2 R101.2 R128.2 R133.2 R152.2 R159.2 R161.2 R163.2 R189.2 R194.2 R199.2 R223.2 R256.2 R282.2 R346.1 R367.1 R560.2 R599.2 R607.2 R617.2 R754.2 R1108.1 Y5.2(G1) Y5.4(G2) ; also on sheet 1 2 3 4 11 12 13 14 15 16 17 18 19 20 22 23 24 25 26 27 28 31 32 47 48 49 50 51 52 53 54 55 56 57 58 59 60 61 62 63 64 65 66 67 68 69 70 71 72 73 74 75 77 79 81 82 83 84 86 87 88 92
P1V05_COMBINED: R112.1 R196.1 R202.1 R213.1 R274.1 R281.1 R364.1 R372.1 R592.1 R595.1 R596.1 R633.1 R644.1 R1047.2 R1048.2 R1049.2 R1109.1 ; also on sheet 1 3 4 16 18 19 47 48 50 51 52 54 55 56 63 71 74 75 79 84 92 94
P1V5_PCH: R587.1 U30.BD30(SATA_IREF) ; also on sheet 31 47 49 52 94
P3V3: R6.1 R86.1 R113.1 R127.1 R147.1 R160.1 R165.1 R167.1 R205.1 R490.1 R546.1 R1055.1 R1056.1 ; also on sheet 4 19 20 32 47 49 50 52 55 56 63 67 74 77 81
P3V3_STBY: R139.1 ; also on sheet 3 4 13 14 16 18 19 20 22 24 25 26 27 28 31 32 52 55 56 57 58 59 62 63 64 65 67 68 69 70 71 72 73 74 75 77 79 81 82 84 86 87 88 92
P3V_BAT: R42.1 ; also on sheet 13 18 52 63 72
A_USB_RBIAS: R617.1 U30.AG11(USB2_RBIAS) U30.AJ11(USB2_RBIAS_N)
CLK_CPLD_SUSCLK: R133.1 R139.2 ; also on sheet 14 47
FM_ADR_TRIGGER_N_GPIO37: R147.2 R159.1 U30.BL2(SATA3GP_GPIO37)
FM_BIOS_ADV_FUNCTIONS_GPIO36: R127.2 R128.1 U30.BT1(SATA2GP_GPIO36)
FM_CPU2PCH_THROT: R88.1 R112.2 ; also on sheet 47 55
FM_CPU_THROTTLE_N: U30.BN2(SATA4GP_GPIO16) ; also on sheet 67
FM_LVC3_RISER1_ID4_N_PU: U30.BD3(OC7_N_GPIO14) ; also on sheet 16
FM_USB_OC_0_N: U30.BH1(OC0_N_GPIO59) ; also on sheet 16 65
FM_USB_OC_1_N: U30.BE2(OC1_N_GPIO40) ; also on sheet 16 65
FM_USB_OC_2_N: U30.BG4(OC2_N_GPIO41) ; also on sheet 16
FM_USB_OC_3_N: U30.BG2(OC3_N_GPIO42) ; also on sheet 16
FM_USB_OC_4_N: U30.BE4(OC4_N_GPIO43) ; also on sheet 16
FM_USB_OC_5_N: U30.BF3(OC5_N_GPIO9) ; also on sheet 16
FM_USB_OC_6_N: U30.BF1(OC6_N_GPIO10) ; also on sheet 16
KR_A_RX_DN: C494.1 ; also on sheet 12
KR_A_RX_DN_C: C494.2 U30.N62(LAN_KR_RX0_N)
KR_A_RX_DP: C500.1 ; also on sheet 12
KR_A_RX_DP_C: C500.2 U30.R62(LAN_KR_RX0_P)
KR_A_TX_DN: U30.J62(LAN_KR_TX0_N) ; also on sheet 12
KR_A_TX_DP: U30.F62(LAN_KR_TX0_P) ; also on sheet 12
KR_B_RX_DN: C179.1 ; also on sheet 12
KR_B_RX_DN_C: C179.2 U30.T64(LAN_KR_RX1_N)
KR_B_RX_DP: C180.1 ; also on sheet 12
KR_B_RX_DP_C: C180.2 U30.P64(LAN_KR_RX1_P)
KR_B_TX_DN: U30.J66(LAN_KR_TX1_N) ; also on sheet 12
KR_B_TX_DP: U30.F66(LAN_KR_TX1_P) ; also on sheet 12
LAN_MDC1_GBE: U30.V67(LAN_MDC1_LED1_1) ; also on sheet 92
LAN_MDIO0_DIR_GBE: U30.E75(LAN_MDIO_DIR_CTL_0) ; also on sheet 92
LAN_MDIO1_DIR_GBE: U30.N72(LAN_MDIO_DIR_CTL_1) ; also on sheet 92
LAN_MDIO1_GBE: U30.T67(LAN_MDIO1_LED1_0) ; also on sheet 92
LED0_LAN_MDC0_SPEED_1: U30.U69(LAN_MDC0_LED0_1) ; also on sheet 92
LED0_LAN_MDIO0_STAT_ACTVT_0: U30.W69(LAN_MDIO0_LED0_0) ; also on sheet 92
LED_SATA_ACT_N: R6.2 U30.BF14(SATALED_N)
M_A_ACT_N: U30.CF33(DDR0_ACT_N_MA15) ; also on sheet 60
M_A_ALERT_N: U30.CK33(DDR0_ALERT_N_PAR_ERR_N) ; also on sheet 60
M_A_BA<0>: U30.CH52(DDR0_BA0) ; also on sheet 60
M_A_BA<1>: U30.CL51(DDR0_BA1) ; also on sheet 60
M_A_BG<0>: U30.CM33(DDR0_BG0_BA2) ; also on sheet 60
M_A_BG<1>: U30.CD35(DDR0_BG1_MA14) ; also on sheet 60
M_A_CK_DN<0>: U30.CJ47(DDR0_CLK_DN0) ; also on sheet 60
M_A_CK_DN<2>: U30.CG47(DDR0_CLK_DN2) ; also on sheet 60
M_A_CK_DP<0>: U30.CL47(DDR0_CLK_DP0) ; also on sheet 60
M_A_CK_DP<2>: U30.CF45(DDR0_CLK_DP2) ; also on sheet 60
M_A_CKE<0>: U30.CD32(DDR0_CKE0) ; also on sheet 60
M_A_CKE<1>: U30.CG32(DDR0_CKE1) ; also on sheet 60
M_A_CS_N<0>: U30.CL54(DDR0_CS_N0) ; also on sheet 60
M_A_CS_N<1>: U30.CJ58(DDR0_CS_N1) ; also on sheet 60
M_A_DQ<0>: U30.BY2(DDR0_DQ0) ; also on sheet 60
M_A_DQ<1>: U30.BY4(DDR0_DQ1) ; also on sheet 60
M_A_DQ<2>: U30.CD2(DDR0_DQ2) ; also on sheet 60
M_A_DQ<3>: U30.CD4(DDR0_DQ3) ; also on sheet 60
M_A_DQ<4>: U30.BW1(DDR0_DQ4) ; also on sheet 60
M_A_DQ<5>: U30.BW3(DDR0_DQ5) ; also on sheet 60
M_A_DQ<6>: U30.CC1(DDR0_DQ6) ; also on sheet 60
M_A_DQ<7>: U30.CC3(DDR0_DQ7) ; also on sheet 60
M_A_DQ<8>: U30.CC7(DDR0_DQ8) ; also on sheet 60
M_A_DQ<9>: U30.CB9(DDR0_DQ9) ; also on sheet 60
M_A_DQ<10>: U30.CM7(DDR0_DQ10) ; also on sheet 60
M_A_DQ<11>: U30.CL9(DDR0_DQ11) ; also on sheet 60
M_A_DQ<12>: U30.CA7(DDR0_DQ12) ; also on sheet 60
M_A_DQ<13>: U30.BY9(DDR0_DQ13) ; also on sheet 60
M_A_DQ<14>: U30.CK7(DDR0_DQ14) ; also on sheet 60
M_A_DQ<15>: U30.CJ9(DDR0_DQ15) ; also on sheet 60
M_A_DQ<16>: U30.CB13(DDR0_DQ16) ; also on sheet 60
M_A_DQ<17>: U30.CC14(DDR0_DQ17) ; also on sheet 60
M_A_DQ<18>: U30.CL13(DDR0_DQ18) ; also on sheet 60
M_A_DQ<19>: U30.CM14(DDR0_DQ19) ; also on sheet 60
M_A_DQ<20>: U30.BY13(DDR0_DQ20) ; also on sheet 60
M_A_DQ<21>: U30.CA14(DDR0_DQ21) ; also on sheet 60
M_A_DQ<22>: U30.CJ13(DDR0_DQ22) ; also on sheet 60
M_A_DQ<23>: U30.CK14(DDR0_DQ23) ; also on sheet 60
M_A_DQ<24>: U30.CD20(DDR0_DQ24) ; also on sheet 60
M_A_DQ<25>: U30.CB20(DDR0_DQ25) ; also on sheet 60
M_A_DQ<26>: U30.CD28(DDR0_DQ26) ; also on sheet 60
M_A_DQ<27>: U30.CB28(DDR0_DQ27) ; also on sheet 60
M_A_DQ<28>: U30.CF18(DDR0_DQ28) ; also on sheet 60
M_A_DQ<29>: U30.CC18(DDR0_DQ29) ; also on sheet 60
M_A_DQ<30>: U30.CF26(DDR0_DQ30) ; also on sheet 60
M_A_DQ<31>: U30.CC26(DDR0_DQ31) ; also on sheet 60
M_A_DQ<32>: U30.CD66(DDR0_DQ32) ; also on sheet 60
M_A_DQ<33>: U30.CB66(DDR0_DQ33) ; also on sheet 60
M_A_DQ<34>: U30.CD72(DDR0_DQ34) ; also on sheet 60
M_A_DQ<35>: U30.CB72(DDR0_DQ35) ; also on sheet 60
M_A_DQ<36>: U30.CF64(DDR0_DQ36) ; also on sheet 60
M_A_DQ<37>: U30.CC64(DDR0_DQ37) ; also on sheet 60
M_A_DQ<38>: U30.CF71(DDR0_DQ38) ; also on sheet 60
M_A_DQ<39>: U30.CC71(DDR0_DQ39) ; also on sheet 60
M_A_DQ<40>: U30.CL66(DDR0_DQ40) ; also on sheet 60
M_A_DQ<41>: U30.CJ66(DDR0_DQ41) ; also on sheet 60
M_A_DQ<42>: U30.CL72(DDR0_DQ42) ; also on sheet 60
M_A_DQ<43>: U30.CJ72(DDR0_DQ43) ; also on sheet 60
M_A_DQ<44>: U30.CM64(DDR0_DQ44) ; also on sheet 60
M_A_DQ<45>: U30.CK64(DDR0_DQ45) ; also on sheet 60
M_A_DQ<46>: U30.CM71(DDR0_DQ46) ; also on sheet 60
M_A_DQ<47>: U30.CK71(DDR0_DQ47) ; also on sheet 60
M_A_DQ<48>: U30.BT72(DDR0_DQ48) ; also on sheet 60
M_A_DQ<49>: U30.BU71(DDR0_DQ49) ; also on sheet 60
M_A_DQ<50>: U30.BG72(DDR0_DQ50) ; also on sheet 60
M_A_DQ<51>: U30.BH71(DDR0_DQ51) ; also on sheet 60
M_A_DQ<52>: U30.BV72(DDR0_DQ52) ; also on sheet 60
M_A_DQ<53>: U30.BW71(DDR0_DQ53) ; also on sheet 60
M_A_DQ<54>: U30.BJ72(DDR0_DQ54) ; also on sheet 60
M_A_DQ<55>: U30.BL71(DDR0_DQ55) ; also on sheet 60
M_A_DQ<56>: U30.BU67(DDR0_DQ56) ; also on sheet 60
M_A_DQ<57>: U30.BT66(DDR0_DQ57) ; also on sheet 60
M_A_DQ<58>: U30.BH67(DDR0_DQ58) ; also on sheet 60
M_A_DQ<59>: U30.BG66(DDR0_DQ59) ; also on sheet 60
M_A_DQ<60>: U30.BW67(DDR0_DQ60) ; also on sheet 60
M_A_DQ<61>: U30.BV66(DDR0_DQ61) ; also on sheet 60
M_A_DQ<62>: U30.BL67(DDR0_DQ62) ; also on sheet 60
M_A_DQ<63>: U30.BJ66(DDR0_DQ63) ; also on sheet 60
M_A_DQS_DN<0>: U30.CB4(DDR0_DQS_DN0) ; also on sheet 60
M_A_DQS_DN<1>: U30.CH7(DDR0_DQS_DN1) ; also on sheet 60
M_A_DQS_DN<2>: U30.CG13(DDR0_DQS_DN2) ; also on sheet 60
M_A_DQS_DN<3>: U30.CD24(DDR0_DQS_DN3) ; also on sheet 60
M_A_DQS_DN<4>: U30.CD69(DDR0_DQS_DN4) ; also on sheet 60
M_A_DQS_DN<5>: U30.CL69(DDR0_DQS_DN5) ; also on sheet 60
M_A_DQS_DN<6>: U30.BM72(DDR0_DQS_DN6) ; also on sheet 60
M_A_DQS_DN<7>: U30.BN67(DDR0_DQS_DN7) ; also on sheet 60
M_A_DQS_DN<8>: U30.CL24(DDR0_DQS_DN8) ; also on sheet 60
M_A_DQS_DP<0>: U30.CB2(DDR0_DQS_DP0) ; also on sheet 60
M_A_DQS_DP<1>: U30.CG9(DDR0_DQS_DP1) ; also on sheet 60
M_A_DQS_DP<2>: U30.CH14(DDR0_DQS_DP2) ; also on sheet 60
M_A_DQS_DP<3>: U30.CB24(DDR0_DQS_DP3) ; also on sheet 60
M_A_DQS_DP<4>: U30.CB69(DDR0_DQS_DP4) ; also on sheet 60
M_A_DQS_DP<5>: U30.CJ69(DDR0_DQS_DP5) ; also on sheet 60
M_A_DQS_DP<6>: U30.BN71(DDR0_DQS_DP6) ; also on sheet 60
M_A_DQS_DP<7>: U30.BM66(DDR0_DQS_DP7) ; also on sheet 60
M_A_DQS_DP<8>: U30.CJ24(DDR0_DQS_DP8) ; also on sheet 60
M_A_ECC<0>: U30.CL20(DDR0_ECC0) ; also on sheet 60
M_A_ECC<1>: U30.CJ20(DDR0_ECC1) ; also on sheet 60
M_A_ECC<2>: U30.CL28(DDR0_ECC2) ; also on sheet 60
M_A_ECC<3>: U30.CJ28(DDR0_ECC3) ; also on sheet 60
M_A_ECC<4>: U30.CM18(DDR0_ECC4) ; also on sheet 60
M_A_ECC<5>: U30.CK18(DDR0_ECC5) ; also on sheet 60
M_A_ECC<6>: U30.CM26(DDR0_ECC6) ; also on sheet 60
M_A_ECC<7>: U30.CK26(DDR0_ECC7) ; also on sheet 60
M_A_MA<0>: U30.CK49(DDR0_MA_0) ; also on sheet 60
M_A_MA<1>: U30.CK41(DDR0_MA_1) ; also on sheet 60
M_A_MA<2>: U30.CM41(DDR0_MA_2) ; also on sheet 60
M_A_MA<3>: U30.CF41(DDR0_MA_3) ; also on sheet 60
M_A_MA<4>: U30.CL39(DDR0_MA_4) ; also on sheet 60
M_A_MA<5>: U30.CG39(DDR0_MA_5) ; also on sheet 60
M_A_MA<6>: U30.CK37(DDR0_MA_6) ; also on sheet 60
M_A_MA<7>: U30.CD39(DDR0_MA_7) ; also on sheet 60
M_A_MA<8>: U30.CM37(DDR0_MA_8) ; also on sheet 60
M_A_MA<9>: U30.CJ35(DDR0_MA_9) ; also on sheet 60
M_A_MA<10>: U30.CJ51(DDR0_MA_10) ; also on sheet 60
M_A_MA<11>: U30.CG35(DDR0_MA_11) ; also on sheet 60
M_A_MA<12>: U30.CF37(DDR0_MA_12) ; also on sheet 60
M_A_MA<13>: U30.CK56(DDR0_MA_13) ; also on sheet 60
M_A_MA<14>: U30.CM52(DDR0_MA14_WE_N) ; also on sheet 60
M_A_MA<15>: U30.CJ54(DDR0_MA15_CAS_N) ; also on sheet 60
M_A_MA<16>: U30.CF49(DDR0_MA16_RAS_N) ; also on sheet 60
M_A_ODT<0>: U30.CF56(DDR0_ODT0) ; also on sheet 60
M_A_ODT<1>: U30.CM60(DDR0_ODT1) ; also on sheet 60
M_A_PAR: U30.CM49(DDR0_PAR) ; also on sheet 60
M_B_ACT_N: U30.CU41(DDR1_ACT_N_MA15) ; also on sheet 61
M_B_ALERT_N: U30.CT42(DDR1_ALERT_N_PAR_ERR_N) ; also on sheet 61
M_B_BA<0>: U30.CR61(DDR1_BA0) ; also on sheet 61
M_B_BA<1>: U30.CT60(DDR1_BA1) ; also on sheet 61
M_B_BG<0>: U30.CR41(DDR1_BG0_BA2) ; also on sheet 61
M_B_BG<1>: U30.CV42(DDR1_BG1_MA14) ; also on sheet 61
M_B_CK_DN<0>: U30.CT58(DDR1_CLK_DN0) ; also on sheet 61
M_B_CK_DN<2>: U30.CR57(DDR1_CLK_DN2) ; also on sheet 61
M_B_CK_DP<0>: U30.CV58(DDR1_CLK_DP0) ; also on sheet 61
M_B_CK_DP<2>: U30.CU57(DDR1_CLK_DP2) ; also on sheet 61
M_B_CKE<0>: U30.CT40(DDR1_CKE0) ; also on sheet 61
M_B_CKE<1>: U30.CV38(DDR1_CKE1) ; also on sheet 61
M_B_CS_N<0>: U30.CR63(DDR1_CS_N0) ; also on sheet 61
M_B_CS_N<1>: U30.CV66(DDR1_CS_N1) ; also on sheet 61
M_B_DQ<0>: U30.CG1(DDR1_DQ0) ; also on sheet 61
M_B_DQ<1>: U30.CG3(DDR1_DQ1) ; also on sheet 61
M_B_DQ<2>: U30.CM3(DDR1_DQ2) ; also on sheet 61
M_B_DQ<3>: U30.CN4(DDR1_DQ3) ; also on sheet 61
M_B_DQ<4>: U30.CF2(DDR1_DQ4) ; also on sheet 61
M_B_DQ<5>: U30.CF4(DDR1_DQ5) ; also on sheet 61
M_B_DQ<6>: U30.CL2(DDR1_DQ6) ; also on sheet 61
M_B_DQ<7>: U30.CK4(DDR1_DQ7) ; also on sheet 61
M_B_DQ<8>: U30.CU8(DDR1_DQ8) ; also on sheet 61
M_B_DQ<9>: U30.CR8(DDR1_DQ9) ; also on sheet 61
M_B_DQ<10>: U30.CU13(DDR1_DQ10) ; also on sheet 61
M_B_DQ<11>: U30.CR13(DDR1_DQ11) ; also on sheet 61
M_B_DQ<12>: U30.CU5(DDR1_DQ12) ; also on sheet 61
M_B_DQ<13>: U30.CT7(DDR1_DQ13) ; also on sheet 61
M_B_DQ<14>: U30.CV12(DDR1_DQ14) ; also on sheet 61
M_B_DQ<15>: U30.CT12(DDR1_DQ15) ; also on sheet 61
M_B_DQ<16>: U30.CV16(DDR1_DQ16) ; also on sheet 61
M_B_DQ<17>: U30.CT16(DDR1_DQ17) ; also on sheet 61
M_B_DQ<18>: U30.CV20(DDR1_DQ18) ; also on sheet 61
M_B_DQ<19>: U30.CT20(DDR1_DQ19) ; also on sheet 61
M_B_DQ<20>: U30.CU15(DDR1_DQ20) ; also on sheet 61
M_B_DQ<21>: U30.CR15(DDR1_DQ21) ; also on sheet 61
M_B_DQ<22>: U30.CU19(DDR1_DQ22) ; also on sheet 61
M_B_DQ<23>: U30.CR19(DDR1_DQ23) ; also on sheet 61
M_B_DQ<24>: U30.CU24(DDR1_DQ24) ; also on sheet 61
M_B_DQ<25>: U30.CR24(DDR1_DQ25) ; also on sheet 61
M_B_DQ<26>: U30.CU28(DDR1_DQ26) ; also on sheet 61
M_B_DQ<27>: U30.CR28(DDR1_DQ27) ; also on sheet 61
M_B_DQ<28>: U30.CV23(DDR1_DQ28) ; also on sheet 61
M_B_DQ<29>: U30.CT23(DDR1_DQ29) ; also on sheet 61
M_B_DQ<30>: U30.CV27(DDR1_DQ30) ; also on sheet 61
M_B_DQ<31>: U30.CT27(DDR1_DQ31) ; also on sheet 61
M_B_DQ<32>: U30.CT73(DDR1_DQ32) ; also on sheet 61
M_B_DQ<33>: U30.CU74(DDR1_DQ33) ; also on sheet 61
M_B_DQ<34>: U30.CJ78(DDR1_DQ34) ; also on sheet 61
M_B_DQ<35>: U30.CJ76(DDR1_DQ35) ; also on sheet 61
M_B_DQ<36>: U30.CU71(DDR1_DQ36) ; also on sheet 61
M_B_DQ<37>: U30.CR71(DDR1_DQ37) ; also on sheet 61
M_B_DQ<38>: U30.CL77(DDR1_DQ38) ; also on sheet 61
M_B_DQ<39>: U30.CK75(DDR1_DQ39) ; also on sheet 61
M_B_DQ<40>: U30.CF77(DDR1_DQ40) ; also on sheet 61
M_B_DQ<41>: U30.CF75(DDR1_DQ41) ; also on sheet 61
M_B_DQ<42>: U30.CB77(DDR1_DQ42) ; also on sheet 61
M_B_DQ<43>: U30.CB75(DDR1_DQ43) ; also on sheet 61
M_B_DQ<44>: U30.CG78(DDR1_DQ44) ; also on sheet 61
M_B_DQ<45>: U30.CG76(DDR1_DQ45) ; also on sheet 61
M_B_DQ<46>: U30.CC78(DDR1_DQ46) ; also on sheet 61
M_B_DQ<47>: U30.CC76(DDR1_DQ47) ; also on sheet 61
M_B_DQ<48>: U30.BW78(DDR1_DQ48) ; also on sheet 61
M_B_DQ<49>: U30.BW76(DDR1_DQ49) ; also on sheet 61
M_B_DQ<50>: U30.BP78(DDR1_DQ50) ; also on sheet 61
M_B_DQ<51>: U30.BP76(DDR1_DQ51) ; also on sheet 61
M_B_DQ<52>: U30.BY77(DDR1_DQ52) ; also on sheet 61
M_B_DQ<53>: U30.BY75(DDR1_DQ53) ; also on sheet 61
M_B_DQ<54>: U30.BR77(DDR1_DQ54) ; also on sheet 61
M_B_DQ<55>: U30.BR75(DDR1_DQ55) ; also on sheet 61
M_B_DQ<56>: U30.BL77(DDR1_DQ56) ; also on sheet 61
M_B_DQ<57>: U30.BL75(DDR1_DQ57) ; also on sheet 61
M_B_DQ<58>: U30.BG77(DDR1_DQ58) ; also on sheet 61
M_B_DQ<59>: U30.BG75(DDR1_DQ59) ; also on sheet 61
M_B_DQ<60>: U30.BM78(DDR1_DQ60) ; also on sheet 61
M_B_DQ<61>: U30.BM76(DDR1_DQ61) ; also on sheet 61
M_B_DQ<62>: U30.BH78(DDR1_DQ62) ; also on sheet 61
M_B_DQ<63>: U30.BH76(DDR1_DQ63) ; also on sheet 61
M_B_DQS_DN<0>: U30.CJ1(DDR1_DQS_DN0) ; also on sheet 61
M_B_DQS_DN<1>: U30.CU10(DDR1_DQS_DN1) ; also on sheet 61
M_B_DQS_DN<2>: U30.CV18(DDR1_DQS_DN2) ; also on sheet 61
M_B_DQS_DN<3>: U30.CU26(DDR1_DQS_DN3) ; also on sheet 61
M_B_DQS_DN<4>: U30.CM76(DDR1_DQS_DN4) ; also on sheet 61
M_B_DQS_DN<5>: U30.CD77(DDR1_DQS_DN5) ; also on sheet 61
M_B_DQS_DN<6>: U30.BT78(DDR1_DQS_DN6) ; also on sheet 61
M_B_DQS_DN<7>: U30.BJ77(DDR1_DQS_DN7) ; also on sheet 61
M_B_DQS_DN<8>: U30.CV34(DDR1_DQS_DN8) ; also on sheet 61
M_B_DQS_DP<0>: U30.CJ3(DDR1_DQS_DP0) ; also on sheet 61
M_B_DQS_DP<1>: U30.CR10(DDR1_DQS_DP1) ; also on sheet 61
M_B_DQS_DP<2>: U30.CT18(DDR1_DQS_DP2) ; also on sheet 61
M_B_DQS_DP<3>: U30.CR26(DDR1_DQS_DP3) ; also on sheet 61
M_B_DQS_DP<4>: U30.CN75(DDR1_DQS_DP4) ; also on sheet 61
M_B_DQS_DP<5>: U30.CD75(DDR1_DQS_DP5) ; also on sheet 61
M_B_DQS_DP<6>: U30.BT76(DDR1_DQS_DP6) ; also on sheet 61
M_B_DQS_DP<7>: U30.BJ75(DDR1_DQS_DP7) ; also on sheet 61
M_B_DQS_DP<8>: U30.CT34(DDR1_DQS_DP8) ; also on sheet 61
M_B_ECC<0>: U30.CV31(DDR1_ECC0) ; also on sheet 61
M_B_ECC<1>: U30.CT31(DDR1_ECC1) ; also on sheet 61
M_B_ECC<2>: U30.CV36(DDR1_ECC2) ; also on sheet 61
M_B_ECC<3>: U30.CT36(DDR1_ECC3) ; also on sheet 61
M_B_ECC<4>: U30.CU30(DDR1_ECC4) ; also on sheet 61
M_B_ECC<5>: U30.CR30(DDR1_ECC5) ; also on sheet 61
M_B_ECC<6>: U30.CU35(DDR1_ECC6) ; also on sheet 61
M_B_ECC<7>: U30.CR35(DDR1_ECC7) ; also on sheet 61
M_B_MA<0>: U30.CV60(DDR1_MA_0) ; also on sheet 61
M_B_MA<1>: U30.CU50(DDR1_MA_1) ; also on sheet 61
M_B_MA<2>: U30.CR50(DDR1_MA_2) ; also on sheet 61
M_B_MA<3>: U30.CT49(DDR1_MA_3) ; also on sheet 61
M_B_MA<4>: U30.CV49(DDR1_MA_4) ; also on sheet 61
M_B_MA<5>: U30.CR48(DDR1_MA_5) ; also on sheet 61
M_B_MA<6>: U30.CT47(DDR1_MA_6) ; also on sheet 61
M_B_MA<7>: U30.CR46(DDR1_MA_7) ; also on sheet 61
M_B_MA<8>: U30.CV47(DDR1_MA_8) ; also on sheet 61
M_B_MA<9>: U30.CT44(DDR1_MA_9) ; also on sheet 61
M_B_MA<10>: U30.CU61(DDR1_MA_10) ; also on sheet 61
M_B_MA<11>: U30.CU46(DDR1_MA_11) ; also on sheet 61
M_B_MA<12>: U30.CV44(DDR1_MA_12) ; also on sheet 61
M_B_MA<13>: U30.CT66(DDR1_MA_13) ; also on sheet 61
M_B_MA<14>: U30.CV62(DDR1_MA14_WE_N) ; also on sheet 61
M_B_MA<15>: U30.CT64(DDR1_MA15_CAS_N) ; also on sheet 61
M_B_MA<16>: U30.CT62(DDR1_MA16_RAS_N) ; also on sheet 61
M_B_ODT<0>: U30.CV64(DDR1_ODT0) ; also on sheet 61
M_B_ODT<1>: U30.CR69(DDR1_ODT1) ; also on sheet 61
M_B_PAR: U30.CR59(DDR1_PAR) ; also on sheet 61
NC_NCSI_ARB_IN: U30.AA77(LAN_NCSI_ARB_IN)
NC_NCSI_BDE_CRS_DV: U30.V74(LAN_NCSI_CRS_DV)
NCSI_BDE_RXD0_R: R196.2 R199.1 U30.Y71(LAN_NCSI_RXD0)
NCSI_BDE_RXD1_R: R281.2 R282.1 U30.W72(LAN_NCSI_RXD1)
NCSI_BDE_TRI_EN_PECI_ID[1]: R256.1 R274.2 U30.AD78(LAN_NCSI_TRI_EN_PECI_ID1)
PD_BIST_ENABLE: R595.2 R599.1 ; also on sheet 47
PD_DMI_RX_TERMINATION: R205.2 R223.1 ; also on sheet 47
PD_GPIO52_CPUSV: R160.2 R161.1 ; also on sheet 47
PD_GPIO53_GSXDIN: R546.2 R560.1 ; also on sheet 47
PD_LAN_NCSI_CLKIN_TXD0_1_EN: R189.1 U30.AA72(LAN_NCSI_CLK_IN) U30.AA75(LAN_NCSI_TX_EN) U30.W77(LAN_NCSI_TXD0) U30.Y78(LAN_NCSI_TXD1)
PD_LAN_SDP0_0: R367.2 U30.G74(LAN_JTCK_SDP0_0)
PD_LAN_SDP1_1: R346.2 U30.N69(LAN_JRST_N_SDP1_1)
PD_NCSI_ARB_OUT: R1108.2 R1109.2 U30.AB78(LAN_NCSI_ARB_OUT)
PD_SPEAKER_PCH: R152.1 R167.2 ; also on sheet 47
PD_TXT_AGENT: R592.2 R607.1 ; also on sheet 47
PD_TXT_PLTEN: R194.1 ; also on sheet 47
PU_GPIO51_GSXDOUT: R163.1 R165.2 ; also on sheet 47
PU_KR_PHY_RBIAS: R644.2 U30.P56(LAN_RBIAS)
PU_LAN_I2C_SDA1_SCL1: R1048.1 U30.P71(LAN_I2C_SCL1) U30.T71(LAN_I2C_SDA1)
PU_LAN_SDP0_1: R372.2 U30.C76(LAN_JTMS_SDP0_1)
PU_LAN_SDP1_0: R364.2 U30.F76(LAN_JTDI_SDP1_0)
PU_SAFE_MODE_BOOT: R633.2 ; also on sheet 47
PU_SATA_RCOMP: R587.2 U30.BB32(SATA_RCOMP)
PU_SGPIO_SATA_DATAOUT1: R86.2 U30.BT16(SDATAOUT1_GPIO48)
RST_PCIE_PCH_N_GPIO19: R101.1 R113.2 U30.BT3(SATA1GP_GPIO19)
RST_SRTCRST_N: C64.1 R42.2 R45.1 ; also on sheet 47
SATA_RX_DN<0>: U30.CA33(SATA_RX_DN0) ; also on sheet 65
SATA_RX_DP<0>: U30.BY32(SATA_RX_DP0) ; also on sheet 65
SATA_TX_DN<0>: U30.BV28(SATA_TX_DN0) ; also on sheet 65
SATA_TX_DP<0>: U30.BW26(SATA_TX_DP0) ; also on sheet 65
SGPIO_SATA_CLOCK: R490.2 R555.1
SGPIO_SATA_CLOCK_R: R555.2 U30.BN14(SCLOCK_GPIO22)
SGPIO_SATA_DATAOUT0: R102.2 R1056.2
SGPIO_SATA_DATAOUT0_R: R102.1 U30.BU18(SDATAOUT0_GPIO39)
SGPIO_SATA_LOAD: R535.1 R1055.2
SGPIO_SATA_LOAD_R: R535.2 U30.BP13(SLOAD_GPIO38)
SMB_GBE_MDIO0_CLK: R1047.1 U30.R72(LAN_I2C_SCL0)
SMB_GBE_MDIO0_DAT: R1049.1 U30.U72(LAN_I2C_SDA0)
SMB_LAN_ALRT_N: R596.2 U30.AN71(LAN_SMBALRT_N) ; also on sheet 75
SMB_LAN_CLK: R202.2 U30.AM75(LAN_SMBCLK) ; also on sheet 75
SMB_LAN_DAT: R213.2 U30.AM77(LAN_SMBDATA) ; also on sheet 75
SPI_10GBE_CLK: R344.2 ; also on sheet 79
SPI_10GBE_CS_N: R1340.2 ; also on sheet 79
SPI_10GBE_CS_N_R: R1340.1 U30.P67(LAN_FLSH_CS_N)
SPI_10GBE_MISO: R754.1 U30.D74(LAN_FLSH_DO) ; also on sheet 79
SPI_10GBE_MOSI: R744.2 ; also on sheet 79
SPI_CLK_R_GBE: R344.1 U30.M67(LAN_FLSH_CLK)
SPI_MOSI_R_GBE: R744.1 U30.C73(LAN_FLSH_DI)
TP_FM_SATA0GP_GP21: U30.BR2(SATA0GP_GPIO21)
TP_FM_XDP_PCH_OBSDATA_D<1>: U30.BM1(SATA5GP_GPIO49)
TP_LAN_JTDO_SPARE5: U30.B71(LAN_JTDO)
TP_LAN_KX4_RX0_N_L0: U30.B50(LAN_KX4_RX0_L0_N)
TP_LAN_KX4_RX0_N_L1: U30.A51(LAN_KX4_RX0_L1_N)
TP_LAN_KX4_RX0_N_L2: U30.B52(LAN_KX4_RX0_L2_N)
TP_LAN_KX4_RX0_N_L3: U30.A53(LAN_KX4_RX0_L3_N)
TP_LAN_KX4_RX0_P_L0: U30.D50(LAN_KX4_RX0_L0_P)
TP_LAN_KX4_RX0_P_L1: U30.C51(LAN_KX4_RX0_L1_P)
TP_LAN_KX4_RX0_P_L2: U30.D52(LAN_KX4_RX0_L2_P)
TP_LAN_KX4_RX0_P_L3: U30.C53(LAN_KX4_RX0_L3_P)
TP_LAN_KX4_RX1_N_L0: U30.B57(LAN_KX4_RX1_L0_N)
TP_LAN_KX4_RX1_N_L1: U30.A58(LAN_KX4_RX1_L1_N)
TP_LAN_KX4_RX1_N_L2: U30.B59(LAN_KX4_RX1_L2_N)
TP_LAN_KX4_RX1_N_L3: U30.A60(LAN_KX4_RX1_L3_N)
TP_LAN_KX4_RX1_P_L0: U30.D57(LAN_KX4_RX1_L0_P)
TP_LAN_KX4_RX1_P_L1: U30.C58(LAN_KX4_RX1_L1_P)
TP_LAN_KX4_RX1_P_L2: U30.D59(LAN_KX4_RX1_L2_P)
TP_LAN_KX4_RX1_P_L3: U30.C60(LAN_KX4_RX1_L3_P)
TP_LAN_KX4_TX0_N_L0: U30.A62(LAN_KX4_TX0_L0_N)
TP_LAN_KX4_TX0_N_L1: U30.B63(LAN_KX4_TX0_L1_N)
TP_LAN_KX4_TX0_N_L2: U30.A64(LAN_KX4_TX0_L2_N)
TP_LAN_KX4_TX0_N_L3: U30.B65(LAN_KX4_TX0_L3_N)
TP_LAN_KX4_TX0_P_L0: U30.C62(LAN_KX4_TX0_L0_P)
TP_LAN_KX4_TX0_P_L1: U30.D63(LAN_KX4_TX0_L1_P)
TP_LAN_KX4_TX0_P_L2: U30.C64(LAN_KX4_TX0_L2_P)
TP_LAN_KX4_TX0_P_L3: U30.D65(LAN_KX4_TX0_L3_P)
TP_LAN_KX4_TX1_N_L0: U30.B67(LAN_KX4_TX1_L0_N)
TP_LAN_KX4_TX1_N_L1: U30.A68(LAN_KX4_TX1_L1_N)
TP_LAN_KX4_TX1_N_L2: U30.B69(LAN_KX4_TX1_L2_N)
TP_LAN_KX4_TX1_N_L3: U30.A70(LAN_KX4_TX1_L3_N)
TP_LAN_KX4_TX1_P_L0: U30.D67(LAN_KX4_TX1_L0_P)
TP_LAN_KX4_TX1_P_L1: U30.C68(LAN_KX4_TX1_L1_P)
TP_LAN_KX4_TX1_P_L2: U30.D69(LAN_KX4_TX1_L2_P)
TP_LAN_KX4_TX1_P_L3: U30.C70(LAN_KX4_TX1_L3_P)
USB2_P0_DN: U30.AD3(USB2_DN0) ; also on sheet 13
USB2_P0_DP: U30.AD1(USB2_DP0) ; also on sheet 13
USB2_P1_DN: U30.AK9(USB2_DN1) ; also on sheet 13
USB2_P1_DP: U30.AH9(USB2_DP1) ; also on sheet 13
USB2_P2_DN: U30.AE4(USB2_DN2) ; also on sheet 13
USB2_P2_DP: U30.AE2(USB2_DP2) ; also on sheet 13
USB2_P3_DN: U30.AG7(USB2_DN3) ; also on sheet 13
USB2_P3_DP: U30.AJ7(USB2_DP3) ; also on sheet 13
USB3_RX_P1_DN: U30.D19(USB3_RX_DN1) ; also on sheet 66
USB3_RX_P1_DP: U30.B19(USB3_RX_DP1) ; also on sheet 66
USB3_RX_P2_DN: U30.C18(USB3_RX_DN2) ; also on sheet 66
USB3_RX_P2_DP: U30.A18(USB3_RX_DP2) ; also on sheet 66
USB3_TX_P1_DN: C699.2 ; also on sheet 66
USB3_TX_P1_DN_C: C699.1 U30.K18(USB3_TX_DN1)
USB3_TX_P1_DP: C703.2 ; also on sheet 66
USB3_TX_P1_DP_C: C703.1 U30.H18(USB3_TX_DP1)
USB3_TX_P2_DN: C700.2 ; also on sheet 66
USB3_TX_P2_DN_C: C700.1 U30.J16(USB3_TX_DN2)
USB3_TX_P2_DP: C704.2 ; also on sheet 66
USB3_TX_P2_DP_C: C704.1 U30.F16(USB3_TX_DP2)
XTAL_KR_PHY_REFCLK_IN: R356.2 U30.J58(LAN_XTAL_IN)
XTAL_KR_PHY_REFCLK_IN_R: C681.1 R356.1 Y5.1(X1)
XTAL_KR_PHY_REFCLK_OUT: C682.1 U30.F58(LAN_XTAL_OUT) Y5.3(X2)

Not connected (* = marked no-connect by the designer): U30 A16(USB3_RX_DP6)* B17(USB3_RX_DP5)* BG28(SATA_TX_DN5)* BH26(SATA_TX_DP5)* BJ28(SATA_TX_DN4)* BJ32(SATA_RX_DP5)* BK76(DDR1_DQS_DN16)* BK78(DDR1_DQS_DP16)* BL26(SATA_TX_DP4)* BL33(SATA_RX_DN5)* BM28(SATA_TX_DN3)* BM32(SATA_RX_DP4)* BN26(SATA_TX_DP3)* BN33(SATA_RX_DN4)* BP28(SATA_TX_DN2)* BP32(SATA_RX_DP3)* BP66(DDR0_DQS_DN16)* BP72(DDR0_DQS_DP15)* BR26(SATA_TX_DP2)* BR33(SATA_RX_DN3)* BR67(DDR0_DQS_DP16)* BR71(DDR0_DQS_DN15)* BT28(SATA_TX_DN1) BT32(SATA_RX_DP2)* BU26(SATA_TX_DP1) BU33(SATA_RX_DN2)* BU75(DDR1_DQS_DN15)* BU77(DDR1_DQS_DP15)* BV32(SATA_RX_DP1) BW33(SATA_RX_DN1) C16(USB3_RX_DN6)* CA1(DDR0_DQS_DN9)* CA3(DDR0_DQS_DP9)* CC22(DDR0_DQS_DN12)* CC67(DDR0_DQS_DN13)* CD9(DDR0_DQS_DN10)* CD13(DDR0_DQS_DP11)* CD54(DDR0_CS_N4)* CE76(DDR1_DQS_DN14)* CE78(DDR1_DQS_DP14)* CF7(DDR0_DQS_DP10)* CF14(DDR0_DQS_DN11)* CF22(DDR0_DQS_DP12)* CF52(DDR0_CS_N5)* CF67(DDR0_DQS_DP13)* CH2(DDR1_DQS_DP9)* CH4(DDR1_DQS_DN9)* CH60(DDR0_ODT3)* CJ32(DDR0_CKE3)* CJ43(DDR0_CLK_DP3)* CK22(DDR0_DQS_DN17)* CK45(DDR0_CLK_DP1)* CK67(DDR0_DQS_DN14)* CL32(DDR0_CKE2)* CL43(DDR0_CLK_DN3)* CM22(DDR0_DQS_DP17)* CM45(DDR0_CLK_DN1)* CM56(DDR0_ODT2)* CM67(DDR0_DQS_DP14)* CR17(DDR1_DQS_DN11)* CR32(DDR1_DQS_DN17)* CR54(DDR1_CLK_DN1)* CR65(DDR1_CS_N4)* CR67(DDR1_ODT2)* CR74(DDR1_DQS_DN13)* CR76(DDR1_DQS_DP13)* CT9(DDR1_DQS_DN10)* CT25(DDR1_DQS_DN12)* CT38(DDR1_CKE3)* CT53(DDR1_CLK_DN3)* CT68(DDR1_CS_N5)* CU17(DDR1_DQS_DP11)* CU32(DDR1_DQS_DP17)* CU54(DDR1_CLK_DP1)* CV9(DDR1_DQS_DP10)* CV25(DDR1_DQS_DP12)* CV40(DDR1_CKE2)* CV53(DDR1_CLK_DP3)* CV68(DDR1_ODT3)* D17(USB3_RX_DN5)* F13(USB3_TX_DP6)* H14(USB3_TX_DP5)* J13(USB3_TX_DN6)* K14(USB3_TX_DN5)*

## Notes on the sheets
sheet 40
- RESET BLOCK DIAGRAM
- RESET BLOCK DIAGRAM
sheet 41
- TXT_PLTEN
- GPIO62
- GP52_GSXSLOAD
- 1
- 1
- 0
- TXT_PLTEN: PLATFORM ENABLE STRAP.
  0 = THE PLATFORM IS NOT INTEL TXT ENABLED.
  1 = DEFAULT. THE PLATFORM IS INTEL TXT ENABLED.
- PU: SV BIOS
  PD: NORMAL(DEFAULT)
- PLL ON-DIE VOLTAGE REGULATOR ENABLE.
  ENABLED WHEN SAMPLED HIGH (DEFAULT).
  DISABLED WHEN SAMPLED LOW.
  WEAK INTERNAL PU (15K-40K).
- NCSI_RXD_0
- TXT_AGENT
- 1
- CLEAR TPM REGISTERS
- 1
- 1
- TXT AGENT (DRIVES TXT TRANSANCTIONS):
  1 = CPU IS TXT_AGENT
  0 = CPU IS NOT TXT_AGENT
- Pull-up : METAL KEY
  Pull-down : UNIQUE KEY
  FOR PC BASED FUSED UNITS THE DEFAULT WILL BE pull-down.
  NCSI_RXD_0 NOW HAS pull-up AS THE DEFAULT.
- NCSI_RXD_1
- NCSI_ARB_OUT
- NCSI_TRI_EN
- 1
- 0
- 0
- ENABLE/DISABLE MANAGEBILITY TRAFFIC
  DEFAULT LOW - DISABLED
  1'B0 = LAN AVAILABLE IN S5 FOR WOL (DEFAULT)
  1'B1 = LAN NOT AVAILABLE IN S5. MANAGEBILITY DISABLED
  NO ON-DIE PU / PDN
- SELECTS B/W THE COMBINED AND SEPERATE VRS
  1'B1 = USING COMBINED P1V05 VR (DEFAULT)
  1'B0 = ALL RAILS HAVE SEPERATE VRS
- PECI_ID[2:0]=000B
- BDE STRAPPING_1
sheet 42
- SPKR
- GPIO19
- GPIO51
- 0
- 1
- 1
- BOOT BIOS STRAPS (BBS)
- THE SIGNAL HAS A WEAK INTERNAL PULL-DOWN.
  0 = DISABLE "NO REBOOT" MODE.
  1 = ENABLE "NO REBOOT" MODE.
- BIT1
  GP51
- BIT0
  GP19
- DESTINATION
- 0
- 1
- RESERVED
- 1
- 0
- RESERVED
- 1
- 1
- SPI <DEFAULT>
- 0
- 0
- RESERVED
- DESIGN NOTE:   INTERNAL PULL-UP (15K-40K). DISABLED AFTER PLTRST# DEASSERTS.
- GPIO33
- GPIO37
- BIOS_ADV_FUNCTIONS
- 0
- GPIO36
- 0
- 1
- DMI RX TERMINATION WHEN AC-COUPLED MODE:
  0 = DMI RX IS TERMINATED TO VSS.(DEFAULT)
  1 = DMI RX IS TERMINATED TO VCC/2.
- ONLY TAKES EFFECT IF DMI IS CONFIGURED IN DCCOUPLED MODE
  HAS A WEAK INTERNAL PULL-DOWN.
  0 = DMI TX IS TERMINATED TO VSS.(DEFAULT)
  1 = DMI TX IS TERMINATED TO VCC/2.
- CPU2PCH_THROT
- TLS CONFIDENTIALITY
  0 = DISABLE INTEL ME CRPTO TRANSPORT LAYER SECURITY (TLS) CIPHTER SUITE (NO CONFIDENTIALITY)
  1 = ENABLE INTEL ME CRPTO TRANSPORT LAYER SECURITY (TLS) CIPHTER SUITE (WITH CONFIDENTIALITY)(DEFAULT)
- GP53_GSXDIN
- BIST_ENABLE
- SAFE_MODE_BOOT
- 0
- 0
- 1
- 0
- DMI AC OR DC COUPLEING MODE
  0 = DMI IS IN AC-COUPLING MODE
  1 = DMI IS IN DC-COUPLING MODE
- BUILT-IN SELF TEST (BIST):
  1 = BIST ENABLED DEFAULT
  0 = BIST DISABLED
- SAFE MODE BOOT (DISABLE CLOCK GATING):
  1 = SAFE MODE BOOT ENABLED
  0 = SAFE MODE BOOT DISABLED DEFAULT
- Note : BIST_ENABLE has internal pull-up to P1V05_COMBINED.
- DESIGN NOTE :
  The default setting should be checked for each board build
- BDE STRAPPING 2
sheet 43
- BDX-DE DDR4 CHANNEL A
sheet 44
- BDX-DE DDR4 CHANNEL B
sheet 45
- CRB also use 0.5%
- Spec: 20ppm
- BDX-DE 10GBE LAN_1
- BDX-DE 10GBE LAN
sheet 46
- BDX-DE SATA, USB2, USB3
